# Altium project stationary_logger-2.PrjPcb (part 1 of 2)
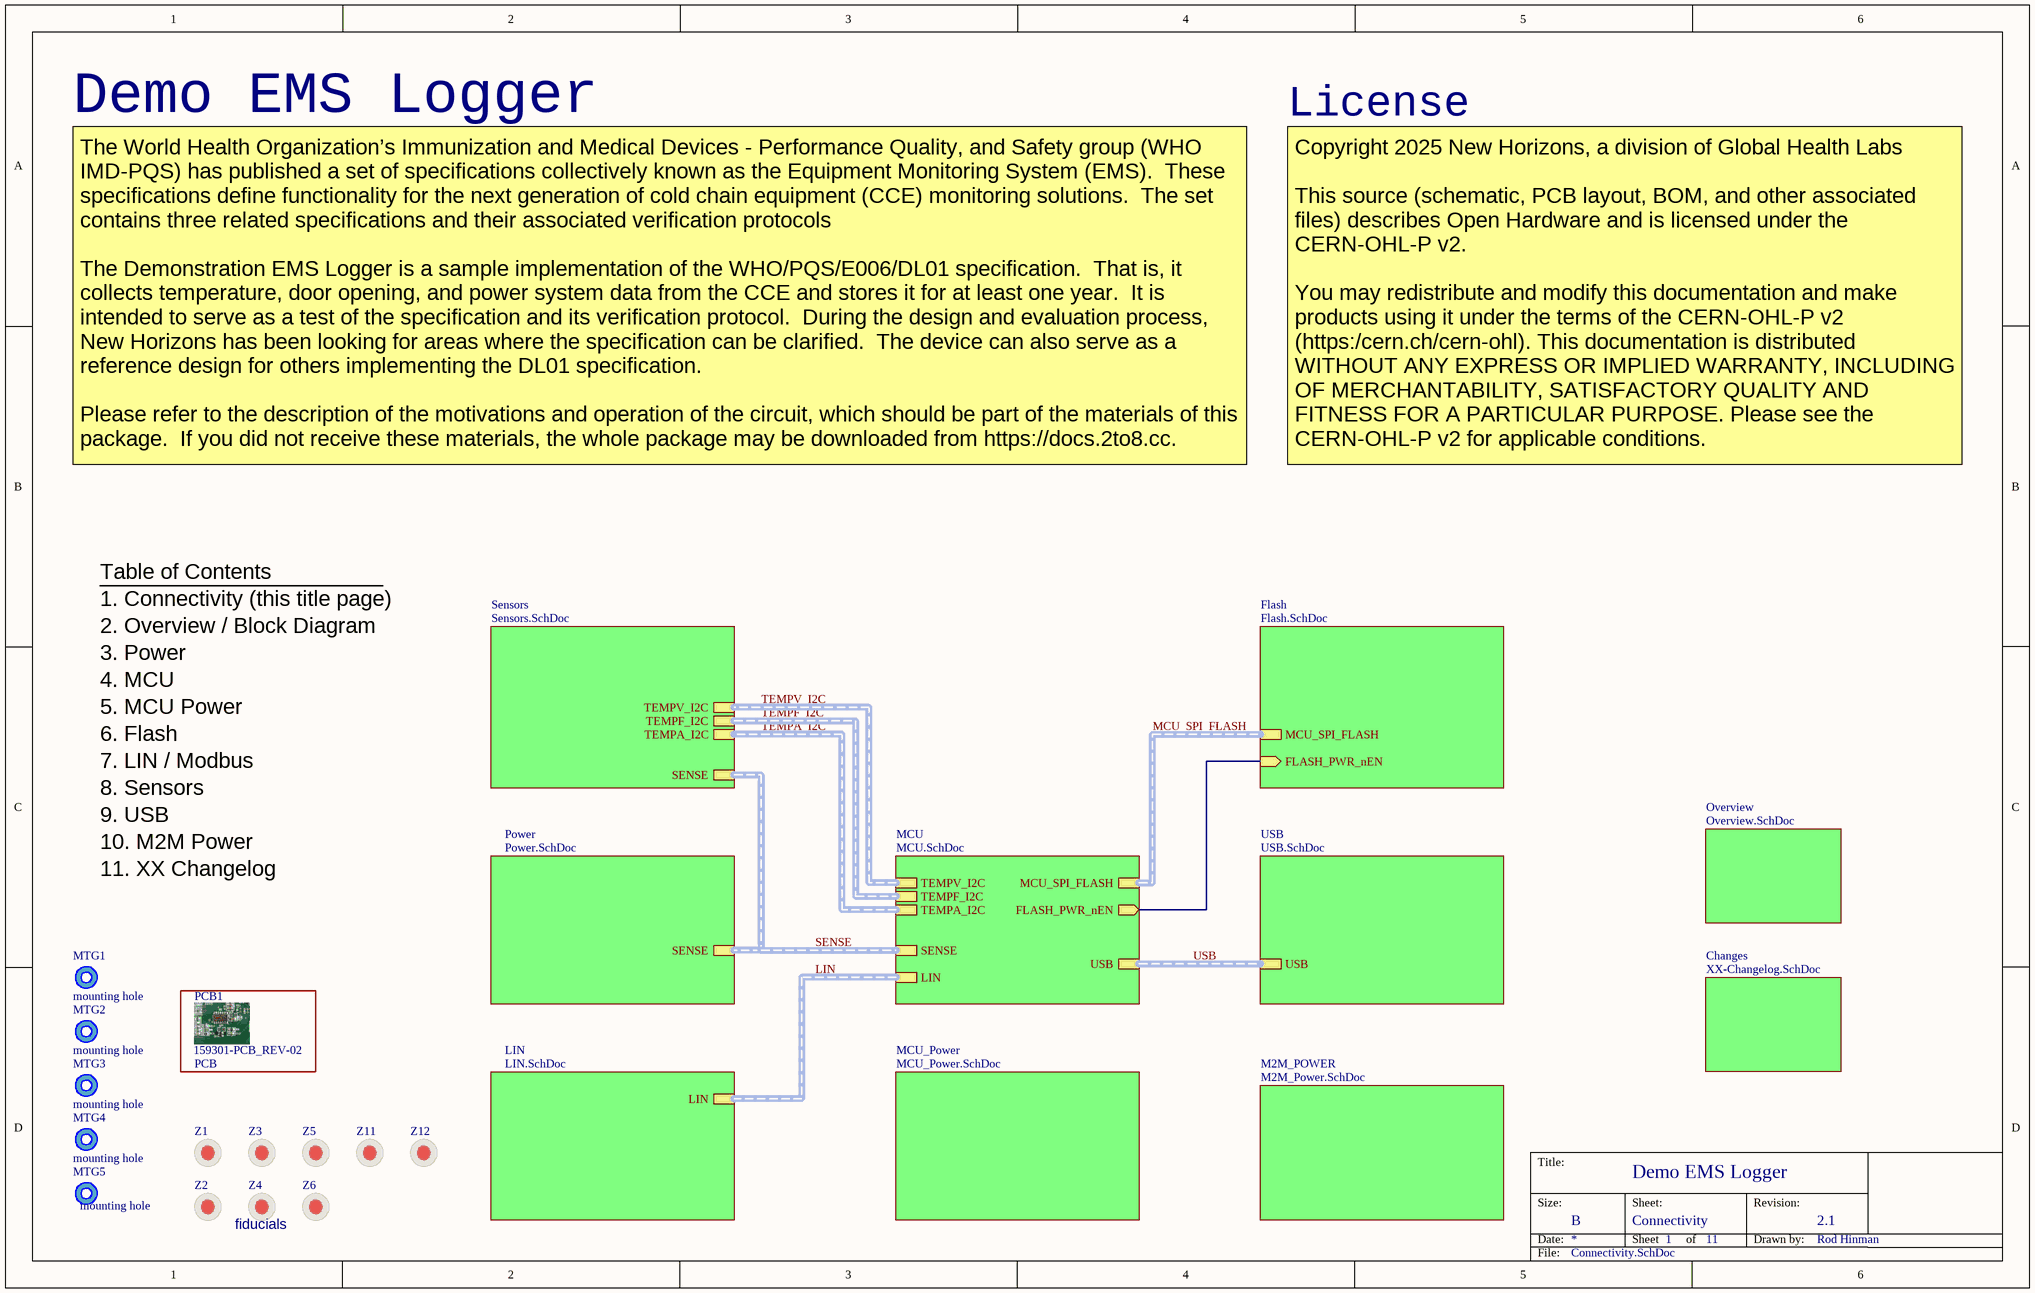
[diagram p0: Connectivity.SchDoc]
nhToday: 2025-05-20; nhProjRev: 2.1; nhProjName: Demo EMS Logger; nhEngPhone: +1 808-989-0977; nhEngName: Rod Hinman; nhEngEmail: rhinman@nhgh.org
11 sheets, 319 parts. Net scope: hierarchical (ports join the sheet entries above them; power ports are global).
Board file: stationary_logger-2.PcbDoc
Sheets:
  Connectivity.SchDoc
    MCU = MCU.SchDoc
    Power = Power.SchDoc
    LIN = LIN.SchDoc
    Sensors = Sensors.SchDoc
    Flash = Flash.SchDoc
    MCU_Power = MCU_Power.SchDoc
    USB = USB.SchDoc
    Changes = XX-Changelog.SchDoc
    Overview = Overview.SchDoc
    M2M_POWER = M2M_Power.SchDoc

## Sheet Connectivity.SchDoc: Insert Title
size B; DrawnBy: Insert Name; Organization: NH-GG; DocumentNumber: 12345; Revision: 1; SheetNumber: 1; SheetTotal: 11; nhSheetName: Connectivity

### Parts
MTG1  mounting hole  [MOUNT_HOLE_3MM_NOCOPPER]  (no BOM)
MTG2  mounting hole  [MOUNT_HOLE_3MM_NOCOPPER]  (no BOM)
MTG3  mounting hole  [MOUNT_HOLE_3MM_NOCOPPER]  (no BOM)
MTG4  mounting hole  [MOUNT_HOLE_3MM_NOCOPPER]  (no BOM)
MTG5  mounting hole  [MOUNT_HOLE_3MM_NOCOPPER]  (no BOM)
PCB1  PCB  manufacturer_pn: 159301-PCB_REV-02  (mechanical)
Z1  NOBOM-00010  [FIDUCIAL_1_3_KEEPOUT]  (value not drawn)  (no BOM)
Z2  NOBOM-00010  [FIDUCIAL_1_3_KEEPOUT]  (value not drawn)  (no BOM)
Z3  NOBOM-00010  [FIDUCIAL_1_3_KEEPOUT]  (value not drawn)  (no BOM)
Z4  NOBOM-00010  [FIDUCIAL_1_3_KEEPOUT]  (value not drawn)  (no BOM)
Z5  NOBOM-00010  [FIDUCIAL_1_3_KEEPOUT]  (value not drawn)  (no BOM)
Z6  NOBOM-00010  [FIDUCIAL_1_3_KEEPOUT]  (value not drawn)  (no BOM)
Z11  NOBOM-00010  [FIDUCIAL_1_3_KEEPOUT]  (value not drawn)  (no BOM)
Z12  NOBOM-00010  [FIDUCIAL_1_3_KEEPOUT]  (value not drawn)  (no BOM)

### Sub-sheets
Changes = XX-Changelog.SchDoc: no entries
Flash = Flash.SchDoc: FLASH_PWR_nEN (in), MCU_SPI_FLASH (harness SPI)
LIN = LIN.SchDoc: LIN (harness lin)
M2M_POWER = M2M_Power.SchDoc: no entries
MCU = MCU.SchDoc: LIN (harness lin), SENSE (harness sense), USB (harness usb), MCU_SPI_FLASH (harness SPI), FLASH_PWR_nEN (out), TEMPF_I2C (harness I2C), TEMPA_I2C (harness I2C), TEMPV_I2C (harness I2C)
MCU_Power = MCU_Power.SchDoc: no entries
Overview = Overview.SchDoc: no entries
Power = Power.SchDoc: SENSE (harness sense)
Sensors = Sensors.SchDoc: TEMPF_I2C (harness I2C), SENSE (harness sense), TEMPA_I2C (harness I2C), TEMPV_I2C (harness I2C)
USB = USB.SchDoc: USB (harness usb)

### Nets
FLASH_PWR_nEN: sheet MCU/FLASH_PWR_nEN, sheet Flash/FLASH_PWR_nEN

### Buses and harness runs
harness LIN = sheet LIN/LIN = sheet MCU/LIN
harness MCU_SPI_FLASH = sheet Flash/MCU_SPI_FLASH = sheet MCU/MCU_SPI_FLASH
harness SENSE = sheet MCU/SENSE = sheet Power/SENSE = sheet Sensors/SENSE
harness TEMPA_I2C = sheet MCU/TEMPA_I2C = sheet Sensors/TEMPA_I2C
harness TEMPF_I2C = sheet MCU/TEMPF_I2C = sheet Sensors/TEMPF_I2C
harness TEMPV_I2C = sheet MCU/TEMPV_I2C = sheet Sensors/TEMPV_I2C
harness USB = sheet MCU/USB = sheet USB/USB

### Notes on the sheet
- Demo EMS Logger
- License
- The World Health Organization’s Immunization and Medical Devices - Performance Quality, and Safety group (WHO IMD-PQS) has published a set of specifications collectively known as the Equipment Monitoring System (EMS).  These specifications define functionality for the next generation of cold chain equipment (CCE) monitoring solutions.  The set contains three related specifications and their associated verification protocols
  The Demonstration EMS Logger is a sample implementation of the WHO/PQS/E006/DL01 specification.  That is, it collects temperature, door opening, and power system data from the CCE and stores it for at least one year.  It is intended to serve as a test of the specification and its verification protocol.  During the design and evaluation process, New Horizons has been looking for areas where the specification can be clarified.  The device can also serve as a reference design for others implementing the DL01 specification.
  Please refer to the description of the motivations and operation of the circuit, which should be part of the materials of this package.  If you did not receive these materials, the whole package may be downloaded from https://docs.2to8.cc.
- Copyright 2025 New Horizons, a division of Global Health Labs
  This source (schematic, PCB layout, BOM, and other associated files) describes Open Hardware and is licensed under the CERN-OHL-P v2.
  You may redistribute and modify this documentation and make products using it under the terms of the CERN-OHL-P v2 (https:/cern.ch/cern-ohl). This documentation is distributed WITHOUT ANY EXPRESS OR IMPLIED WARRANTY, INCLUDING OF MERCHANTABILITY, SATISFACTORY QUALITY AND FITNESS FOR A PARTICULAR PURPOSE. Please see the CERN-OHL-P v2 for applicable conditions.
- Table of Contents
- 1. Connectivity (this title page)
- 2. Overview / Block Diagram
- 3. Power
- 4. MCU
- 6. Flash
- 7. LIN / Modbus
- 5. MCU Power
- 8. Sensors
- 9. USB
- 10. M2M Power
- 11. XX Changelog
- fiducials

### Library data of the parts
MTG1-MTG5 = NOBOM-00023: Mounting hole, 3mm NPT; manufacturer: New Horizons; id: 477843
PCB1 = MECH-00042: PCB - enter your own cost; manufacturer: New Horizons; id: 408762
Z1-Z6 Z11 Z12 = NOBOM-00010: Fiducial, 1mm dia, 3mm solder mask opening; manufacturer: New Horizons; id: 138118

## Sheet MCU.SchDoc: Insert Title
size B; DrawnBy: Insert Name; Organization: NH-GG; DocumentNumber: 12345; Revision: 1; SheetNumber: 4; SheetTotal: 11; nhSheetName: MCU
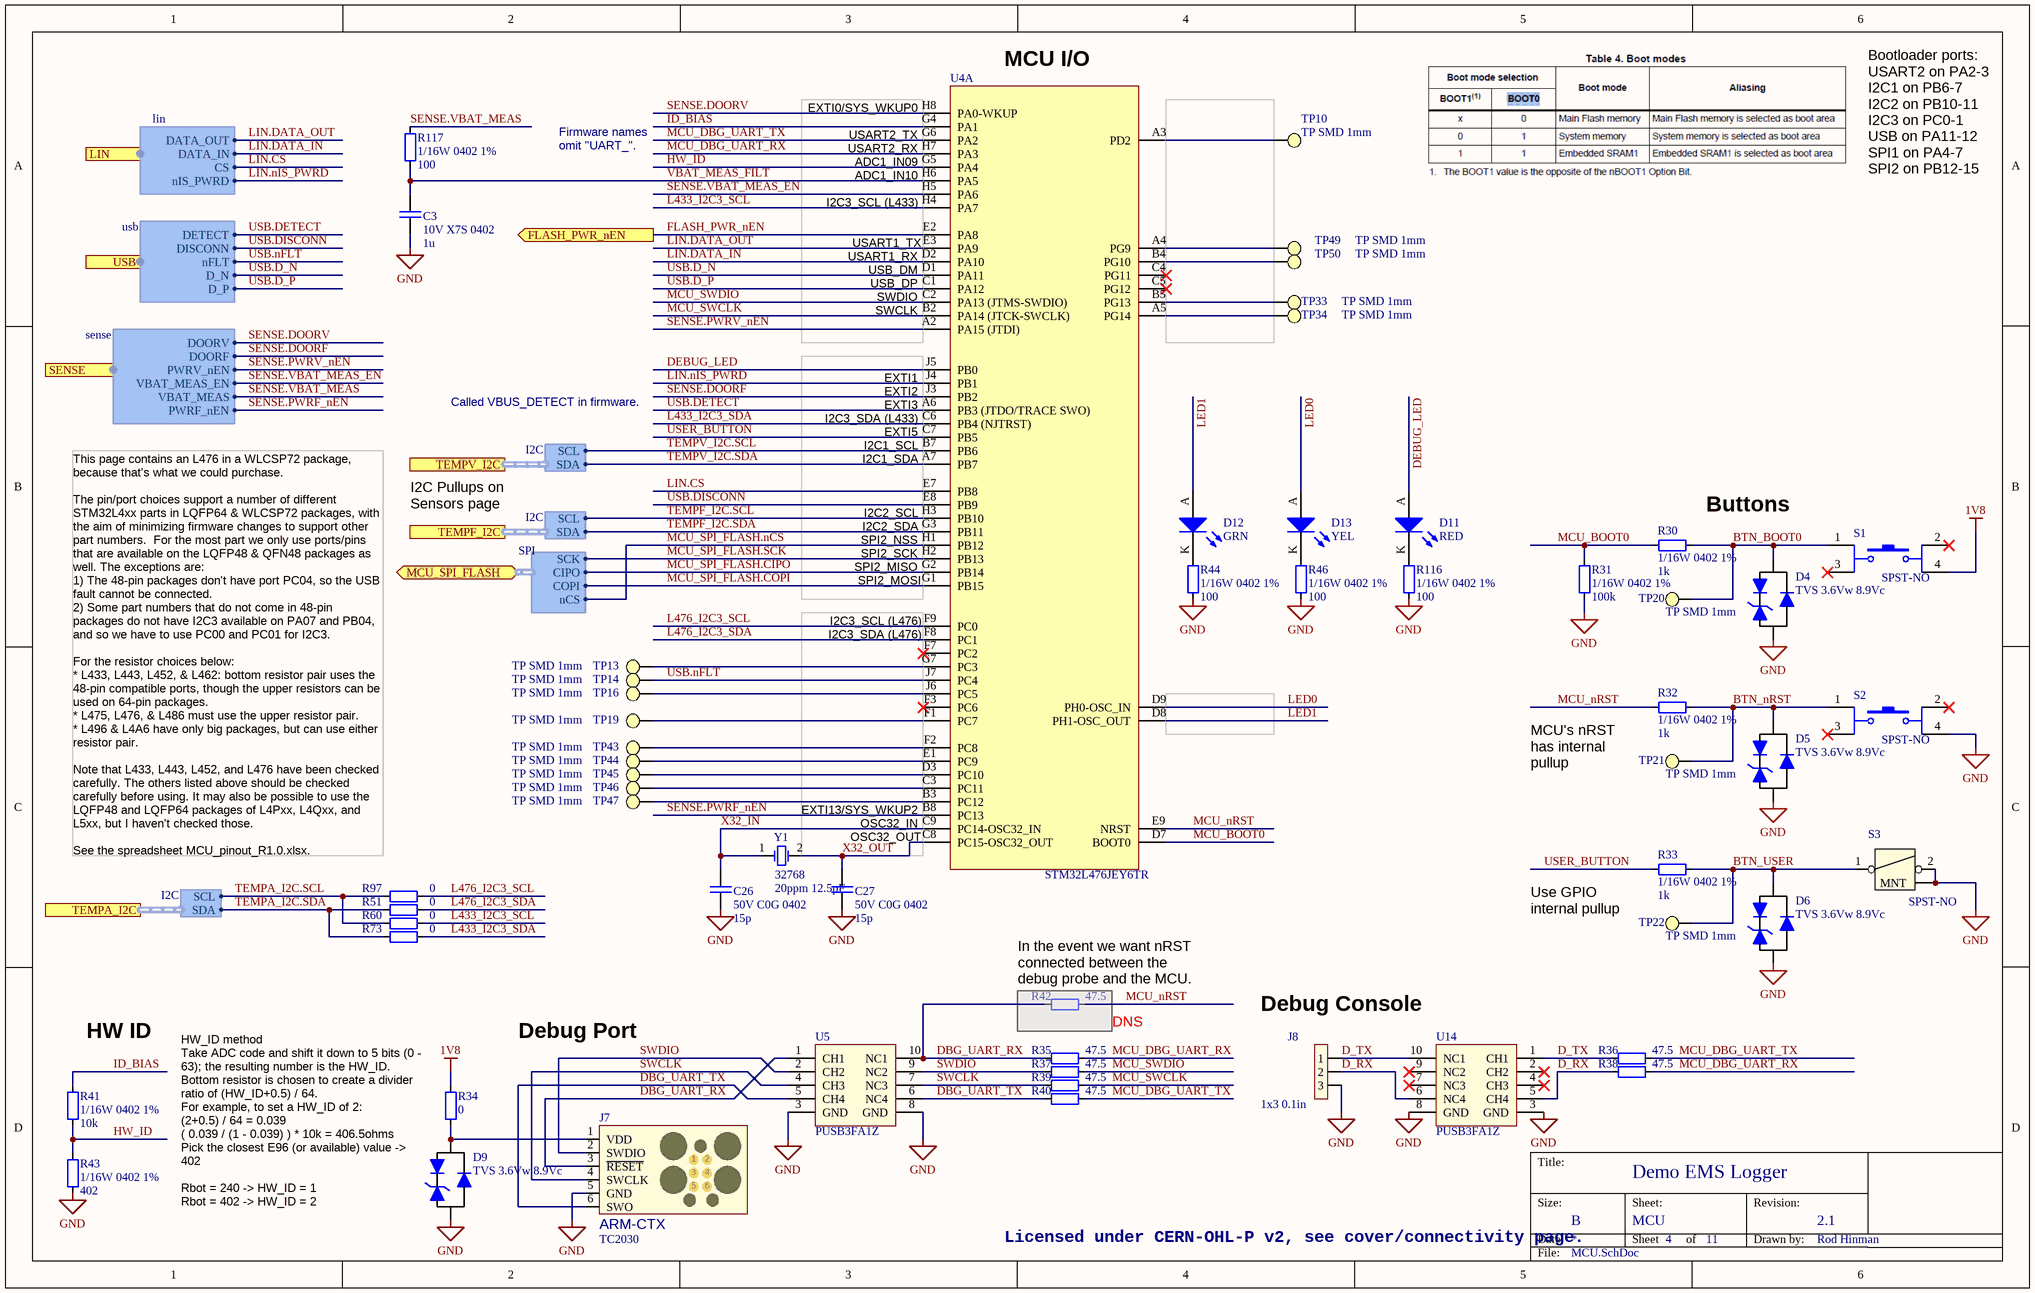
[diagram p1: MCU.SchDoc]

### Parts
C3  10V X7S 0402  value_text: 1u  [CAPC1005X55,0402,L]
C26  50V C0G 0402  value_text: 15p  [CAPC1005X60,0402,L]
C27  50V C0G 0402  value_text: 15p  [CAPC1005X60,0402,L]
D4  TVS 3.6Vw 8.9Vc  [TI_2-X1SON_DFN65P100X60-2L]
D5  TVS 3.6Vw 8.9Vc  [TI_2-X1SON_DFN65P100X60-2L]
D6  TVS 3.6Vw 8.9Vc  [TI_2-X1SON_DFN65P100X60-2L]
D9  TVS 3.6Vw 8.9Vc  [TI_2-X1SON_DFN65P100X60-2L]
D11  RED  [LEDC1005X04NRED,0402,]
D12  GRN  [LEDC1608X06NGRN,0603,]
D13  YEL  [LEDC1608X06NYEL,0603,]
J7  TC2030  [TAG-TC2030-LEGS]  (no BOM)
J8  1x3 0.1in  [HDR_3PIN]
R30  1/16W 0402 1%  value_text: 1k  [RESC1005X40,0402,L]
R31  1/16W 0402 1%  value_text: 100k  [RESC1005X40,0402,L]
R32  1/16W 0402 1%  value_text: 1k  [RESC1005X40,0402,L]
R33  1/16W 0402 1%  value_text: 1k  [RESC1005X40,0402,L]
R34  value_text: 0  [RESC1005X40,0402,L]  (hidden comment: 1/16W 0402 Jumper)
R35  value_text: 47.5  [RESC1005X40,0402,L]  (hidden comment: 1/16W 0402 1%)
R36  value_text: 47.5  [RESC1005X40,0402,L]  (hidden comment: 1/16W 0402 1%)
R37  value_text: 47.5  [RESC1005X40,0402,L]  (hidden comment: 1/16W 0402 1%)
R38  value_text: 47.5  [RESC1005X40,0402,L]  (hidden comment: 1/16W 0402 1%)
R39  value_text: 47.5  [RESC1005X40,0402,L]  (hidden comment: 1/16W 0402 1%)
R40  value_text: 47.5  [RESC1005X40,0402,L]  (hidden comment: 1/16W 0402 1%)
R41  1/16W 0402 1%  value_text: 10k  [RESC1005X40,0402,L]
R42  value_text: 47.5  [RESC1005X40,0402,L]  (hidden comment: 1/16W 0402 1%)
R43  1/16W 0402 1%  value_text: 402  [RESC1005X40,0402,L]
R44  1/16W 0402 1%  value_text: 100  [RESC1005X40,0402,L]
R46  1/16W 0402 1%  value_text: 100  [RESC1005X40,0402,L]
R51  value_text: 0  [RESC1005X40,0402,L]  (hidden comment: 1/16W 0402 Jumper)
R60  value_text: 0  [RESC1005X40,0402,L]  (hidden comment: 1/16W 0402 Jumper)
R73  value_text: 0  [RESC1005X40,0402,L]  (hidden comment: 1/16W 0402 Jumper)
R97  value_text: 0  [RESC1005X40,0402,L]  (hidden comment: 1/16W 0402 Jumper)
R116  1/16W 0402 1%  value_text: 100  [RESC1005X40,0402,L]
R117  1/16W 0402 1%  value_text: 100  [RESC1005X40,0402,L]
S1  SPST-NO  [EVQP2x02W_MIRROR]
S2  SPST-NO  [EVQP2x02W_MIRROR]
S3  SPST-NO  [TE_1571300]
TP10  TP SMD 1mm  [TP_SMD_Ø1.0mm NO SILK]  (no BOM)
TP13  TP SMD 1mm  [TP_SMD_Ø1.0mm NO SILK]  (no BOM)
TP14  TP SMD 1mm  [TP_SMD_Ø1.0mm NO SILK]  (no BOM)
TP16  TP SMD 1mm  [TP_SMD_Ø1.0mm NO SILK]  (no BOM)
TP19  TP SMD 1mm  [TP_SMD_Ø1.0mm NO SILK]  (no BOM)
TP20  TP SMD 1mm  [TP_SMD_Ø1.0mm NO SILK]  (no BOM)
TP21  TP SMD 1mm  [TP_SMD_Ø1.0mm NO SILK]  (no BOM)
TP22  TP SMD 1mm  [TP_SMD_Ø1.0mm NO SILK]  (no BOM)
TP33  TP SMD 1mm  [TP_SMD_Ø1.0mm NO SILK]  (no BOM)
TP34  TP SMD 1mm  [TP_SMD_Ø1.0mm NO SILK]  (no BOM)
TP43  TP SMD 1mm  [TP_SMD_Ø1.0mm NO SILK]  (no BOM)
TP44  TP SMD 1mm  [TP_SMD_Ø1.0mm NO SILK]  (no BOM)
TP45  TP SMD 1mm  [TP_SMD_Ø1.0mm NO SILK]  (no BOM)
TP46  TP SMD 1mm  [TP_SMD_Ø1.0mm NO SILK]  (no BOM)
TP47  TP SMD 1mm  [TP_SMD_Ø1.0mm NO SILK]  (no BOM)
TP49  TP SMD 1mm  [TP_SMD_Ø1.0mm NO SILK]  (no BOM)
TP50  TP SMD 1mm  [TP_SMD_Ø1.0mm NO SILK]  (no BOM)
U4  STM32L476JEY6TR  [STM_BGA72C40P9X9_441X376X58]  (part A of 2)
U5  PUSB3FA1Z  [NEXPERIA_DFN2510_50p250x100x50-10]
U14  PUSB3FA1Z  [NEXPERIA_DFN2510_50p250x100x50-10]
Y1  20ppm 12.5pF  value_text: 32768  [FC-135]

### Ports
FLASH_PWR_nEN (out), LIN (out, harness lin), MCU_SPI_FLASH (bidir, harness SPI), SENSE (out, harness sense), TEMPA_I2C (harness I2C), TEMPF_I2C (harness I2C), TEMPV_I2C (harness I2C), USB (out, harness usb)

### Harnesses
SPI: CIPO, COPI, SCK, nCS
I2C: SCL, SDA
lin: DATA_OUT, DATA_IN, CS, nIS_PWRD
usb: DETECT, DISCONN, D_N, D_P, nFLT
sense: DOORV, DOORF, PWRV_nEN, VBAT_MEAS_EN, VBAT_MEAS, PWRF_nEN

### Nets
1V8: R34.1 S1.4
GND: C3.1 C26.1 C27.1 D4.2 D5.2 D6.2 D9.2 J7.5(GND) J8.3 R31.2 R43.2 R44.1 R46.1 R116.1 S2.4 S3.2 S3.MNT U5.3(GND) U5.8(GND) U14.3(GND) U14.8(GND)
BTN_BOOT0: D4.1 R30.2 S1.1 TP20.1
BTN_nRST: D5.1 R32.2 S2.1 TP21.1
BTN_USER: D6.1 R33.2 S3.1 TP22.1
D_RX: J8.2 R38.1 U14.5(CH4) U14.6(NC4)
D_TX: J8.1 R36.1 U14.1(CH1) U14.10(NC1)
DBG_UART_RX: J7.3(~{RESET}) R35.1 R42.2 U5.1(CH1) U5.10(NC1)
DBG_UART_TX: J7.6(SWO) R40.1 U5.5(CH4) U5.6(NC4)
DEBUG_LED: D11.A U4.J5(PB0)
FLASH_PWR_nEN: U4.E2(PA8) ; port FLASH_PWR_nEN
HW_ID: R41.2 R43.1 U4.G5(PA4)
ID_BIAS: R41.1 U4.G4(PA1)
L433_I2C3_SCL: R60.1 U4.H4(PA7)
L433_I2C3_SDA: R73.1 U4.C6(PB4_(NJTRST))
L476_I2C3_SCL: R97.1 U4.F9(PC0)
L476_I2C3_SDA: R51.1 U4.F8(PC1)
LED0: D13.A U4.D9(PH0-OSC_IN)
LED1: D12.A U4.D8(PH1-OSC_OUT)
LIN.CS: U4.E7(PB8) ; port LIN.CS
LIN.DATA_IN: U4.D2(PA10) ; port LIN.DATA_IN
LIN.DATA_OUT: U4.E3(PA9) ; port LIN.DATA_OUT
LIN.nIS_PWRD: U4.J4(PB1) ; port LIN.nIS_PWRD
MCU_BOOT0: R30.1 R31.1 U4.D7(BOOT0)
MCU_DBG_UART_RX: R35.2 R38.2 U4.H7(PA3)
MCU_DBG_UART_TX: R36.2 R40.2 U4.G6(PA2)
MCU_nRST: R32.1 R42.1 U4.E9(NRST)
MCU_SPI_FLASH.CIPO: U4.G2(PB14) ; port MCU_SPI_FLASH.CIPO
MCU_SPI_FLASH.COPI: U4.G1(PB15) ; port MCU_SPI_FLASH.COPI
MCU_SPI_FLASH.nCS: U4.H1(PB12) ; port MCU_SPI_FLASH.nCS
MCU_SPI_FLASH.SCK: U4.H2(PB13) ; port MCU_SPI_FLASH.SCK
MCU_SWCLK: R39.2 U4.B2(PA14_(JTCK-SWCLK))
MCU_SWDIO: R37.2 U4.C2(PA13_(JTMS-SWDIO))
SENSE.DOORF: U4.J3(PB2) ; port SENSE.DOORF
SENSE.DOORV: U4.H8(PA0-WKUP) ; port SENSE.DOORV
SENSE.PWRF_nEN: U4.B8(PC13) ; port SENSE.PWRF_nEN
SENSE.PWRV_nEN: U4.A2(PA15_(JTDI)) ; port SENSE.PWRV_nEN
SENSE.VBAT_MEAS: R117.2 ; port SENSE.VBAT_MEAS
SENSE.VBAT_MEAS_EN: U4.H5(PA6) ; port SENSE.VBAT_MEAS_EN
SWCLK: J7.4(SWCLK) R39.1 U5.4(CH3) U5.7(NC3)
SWDIO: J7.2(SWDIO) R37.1 U5.2(CH2) U5.9(NC2)
TEMPA_I2C.SCL: R60.2 R97.2 ; port TEMPA_I2C.SCL
TEMPA_I2C.SDA: R51.2 R73.2 ; port TEMPA_I2C.SDA
TEMPF_I2C.SCL: U4.H3(PB10) ; port TEMPF_I2C.SCL
TEMPF_I2C.SDA: U4.G3(PB11) ; port TEMPF_I2C.SDA
TEMPV_I2C.SCL: U4.B7(PB6) ; port TEMPV_I2C.SCL
TEMPV_I2C.SDA: U4.A7(PB7) ; port TEMPV_I2C.SDA
USB.D_N: U4.D1(PA11) ; port USB.D_N
USB.D_P: U4.C1(PA12) ; port USB.D_P
USB.DETECT: U4.A6(PB3_(JTDO/TRACE_SWO)) ; port USB.DETECT
USB.DISCONN: U4.E8(PB9) ; port USB.DISCONN
USB.nFLT: TP14.1 U4.J7(PC4) ; port USB.nFLT
USER_BUTTON: R33.1 U4.C7(PB5)
VBAT_MEAS_FILT: C3.2 R117.1 U4.H6(PA5)
X32_IN: C26.2 U4.C9(PC14-OSC32_IN) Y1.1(OSC1)
X32_OUT: C27.2 U4.C8(PC15-OSC32_OUT) Y1.2(OSC2)
NetD9_1: D9.1 J7.1(VDD) R34.2
NetD11_K: D11.K R116.2
NetD12_K: D12.K R44.2
NetD13_K: D13.K R46.2
NetTP10_1: TP10.1 U4.A3(PD2)
NetTP13_1: TP13.1 U4.G7(PC3)
NetTP16_1: TP16.1 U4.J6(PC5)
NetTP19_1: TP19.1 U4.F1(PC7)
NetTP33_1: TP33.1 U4.B5(PG13)
NetTP34_1: TP34.1 U4.A5(PG14)
NetTP43_1: TP43.1 U4.F2(PC8)
NetTP44_1: TP44.1 U4.E1(PC9)
NetTP45_1: TP45.1 U4.D3(PC10)
NetTP46_1: TP46.1 U4.C3(PC11)
NetTP47_1: TP47.1 U4.B3(PC12)
NetTP49_1: TP49.1 U4.A4(PG9)
NetTP50_1: TP50.1 U4.B4(PG10)

Not connected (* = marked no-connect by the designer): S1 2* 3*; S2 2* 3*; U4 C4(PG11)* C5(PG12)* F3(PC6)* F7(PC2)*; U14 2(CH2)* 4(CH3)* 7(NC3)* 9(NC2)*

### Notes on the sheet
- (near U4) MCU I/O
- Firmware names
- omit "UART_".
- Bootloader ports:
  USART2 on PA2-3
  I2C1 on PB6-7
  I2C2 on PB10-11
  I2C3 on PC0-1
  USB on PA11-12
  SPI1 on PA4-7
  SPI2 on PB12-15
- (near U4) EXTI0/SYS_WKUP0
  USART2_TX
  USART2_RX
  ADC1_IN09
  ADC1_IN10
  I2C3_SCL (L433)
  USART1_TX
  USART1_RX
  USB_DM
  USB_DP
  SWDIO
  SWCLK
- Called VBUS_DETECT in firmware.
- I2C Pullups on Sensors page
- Buttons
- (near U4) EXTI1
  EXTI2
  EXTI3
  I2C3_SDA (L433)
  EXTI5
  I2C1_SCL
  I2C1_SDA
  I2C2_SCL
  I2C2_SDA
  SPI2_NSS
  SPI2_SCK
  SPI2_MISO
  SPI2_MOSI
- MCU's nRST has internal pullup
- This page contains an L476 in a WLCSP72 package, because that's what we could purchase.
  The pin/port choices support a number of different STM32L4xx parts in LQFP64 & WLCSP72 packages, with the aim of minimizing firmware changes to support other part numbers.  For the most part we only use ports/pins that are available on the LQFP48 & QFN48 packages as well. The exceptions are:
  1) The 48-pin packages don't have port PC04, so the USB fault cannot be connected.
  2) Some part numbers that do not come in 48-pin packages do not have I2C3 available on PA07 and PB04, and so we have to use PC00 and PC01 for I2C3.
  For the resistor choices below:
  * L433, L443, L452, & L462: bottom resistor pair uses the 48-pin compatible ports, though the upper resistors can be used on 64-pin packages.
  * L475, L476, & L486 must use the upper resistor pair.
  * L496 & L4A6 have only big packages, but can use either resistor pair.
  Note that L433, L443, L452, and L476 have been checked carefully. The others listed above should be checked carefully before using. It may also be possible to use the LQFP48 and LQFP64 packages of L4Pxx, L4Qxx, and L5xx, but I haven't checked those.
  See the spreadsheet MCU_pinout_R1.0.xlsx.
- (near Y1) I2C3_SCL (L476)
  I2C3_SDA (L476)
  EXTI13/SYS_WKUP2
  OSC32_IN
  OSC32_OUT
- Use GPIO internal pullup
- (near R41) HW ID
- Debug Port
- (near R42) In the event we want nRST connected between the debug probe and the MCU.
- (near R42) DNS
- Debug Console
- HW_ID method
  Take ADC code and shift it down to 5 bits (0 - 63); the resulting number is the HW_ID. Bottom resistor is chosen to create a divider ratio of (HW_ID+0.5) / 64.
  For example, to set a HW_ID of 2:
  (2+0.5) / 64 = 0.039
  ( 0.039 / (1 - 0.039) ) * 10k = 406.5ohms
  Pick the closest E96 (or available) value -> 402
  Rbot = 240 -> HW_ID = 1
  Rbot = 402 -> HW_ID = 2
- Licensed under CERN-OHL-P v2, see cover/connectivity page.

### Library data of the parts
C3 = CAP-00070: 1µF ±10% 10V Ceramic Capacitor X7S 0402 (1005 Metric); manufacturer_pn: GCM155C71A105KE38D; manufacturer: Murata Electronics North America; id: 168187; value: 1E-6
C26 C27 = CAP-00102: 15pF ±1% 50V Ceramic Capacitor C0G, NP0 0402 (1005 Metric); manufacturer_pn: 04025U150FAT2A; manufacturer: AVX Corporation; id: 226036; value: 1.5E-11
D4-D6 D9 = DIO-00055: TVS DIODE 3.6VWM 8.9VC 2X1SON; manufacturer_pn: TPD1E04U04DPYR; manufacturer: Texas Instruments; id: 468103
D11 = LED-00025: LED RED CLEAR 0402 SMD; manufacturer_pn: SML-P12VTT86R; manufacturer: Rohm Semiconductor; id: 468105
D12 = LED-00007: Green 571nm LED Indication - Discrete 2V 0603 (1608 Metric) 35mcd clear; manufacturer_pn: LTST-C191KGKT; manufacturer: Lite-On Inc.; id: 137520
D13 = LED-00006: Yellow 591nm LED Indication - Discrete 2.1V 0603 (1608 Metric) 104mcd clear; manufacturer_pn: LTST-C191KSKT; manufacturer: Lite-On Inc.; id: 137519
J7 = NOBOM-00009: Tag Connect TC2030 LEGS; manufacturer: New Horizons; id: 138117
J8 = CONN-00030: 3 Positions Header, Unshrouded Connector 0.100" (2.54mm) Through Hole Gold; manufacturer_pn: 961103-6404-AR; manufacturer: 3M; id: 137495
R30 R32 R33 = RES-00090: 1k Ohm ±1% 0.063W, 1/16W Chip Resistor 0402 (1005 Metric) Moisture Resistant Thick Film; manufacturer_pn: RC0402FR-071KL; manufacturer: Yageo; id: 168133; value: 1000
R31 = RES-00095: 100k Ohm ±1% 0.063W, 1/16W Chip Resistor 0402 (1005 Metric) Moisture Resistant Thick Film; manufacturer_pn: RC0402FR-07100KL; manufacturer: Yageo; id: 168197; value: 100000
R34 R51 R60 R73 R97 = RES-00093: 0.0 Ohm Jumper 0.063W, 1/16W Chip Resistor 0402 (1005 Metric) Moisture Resistant Thick Film; manufacturer_pn: RC0402JR-070RL; manufacturer: Yageo; id: 168185; value: 0
R35-R40 R42 = RES-00169: 47.5 ±1% 0.063W, 1/16W Chip Resistor 0402 (1005 Metric) - Thick Film; manufacturer_pn: RC0402FR-0747R5L; manufacturer: Yageo; id: 406782; value: 47.5
R41 = RES-00094: 10k Ohm ±1% 0.063W, 1/16W Chip Resistor 0402 (1005 Metric) Moisture Resistant Thick Film; manufacturer_pn: RC0402FR-0710KL; manufacturer: Yageo; id: 168195; value: 10000
R43 = RES-00203: RES 402 OHM 1% 1/16W 0402; manufacturer_pn: RC0402FR-07402RL; manufacturer: Yageo; id: 472313; value: 402; reorder_quantity: 0
R44 R46 R116 R117 = RES-00111: 100 Ohms ±1% 0.063W, 1/16W Chip Resistor 0402 (1005 Metric) Moisture Resistant Thick Film; manufacturer_pn: RC0402FR-07100RL; manufacturer: Yageo; id: 184628; value: 100
S1 S2 = SW-00011: Tactile Switch SPST-NO Top Actuated Surface Mount; manufacturer_pn: EVQ-P2402W; manufacturer: Panasonic Electronic Components; id: 468174
S3 = SW-00012: SWITCH TACTILE SPST-NO 0.05A 24V; manufacturer_pn: 1571300-2; manufacturer: TE Connectivity ALCOSWITCH Switches; id: 477187
TP10 TP13 TP14 TP16 TP19-TP22 TP33 TP34 TP43-TP47 TP49 TP50 = NOBOM-00001: Test point, SMD, 1mm dia (0.040"); manufacturer: New Horizons; id: 137197
U4 = MCU-00028: IC MCU 32BIT 512KB FLASH WLCSP72; manufacturer: STMicroelectronics; id: 474854
U5 U14 = DIO-00056: TVS DIODE 3VC DFN2510A-10; manufacturer: Nexperia USA Inc.; id: 468220
Y1 = XTAL-00000: 32.768kHz ±20ppm Crystal 12.5pF 55 kOhm -40°C ~ 85°C Surface Mount 2-SMD; manufacturer_pn: ABS07L-32.768KHZ-T; manufacturer: Abracon LLC; id: 136552; value: 32768

## Sheet Power.SchDoc: Insert Title
size B; DrawnBy: Insert Name; Organization: NH-GG; DocumentNumber: 12345; Revision: 1; SheetNumber: 3; SheetTotal: 11; nhSheetName: Power
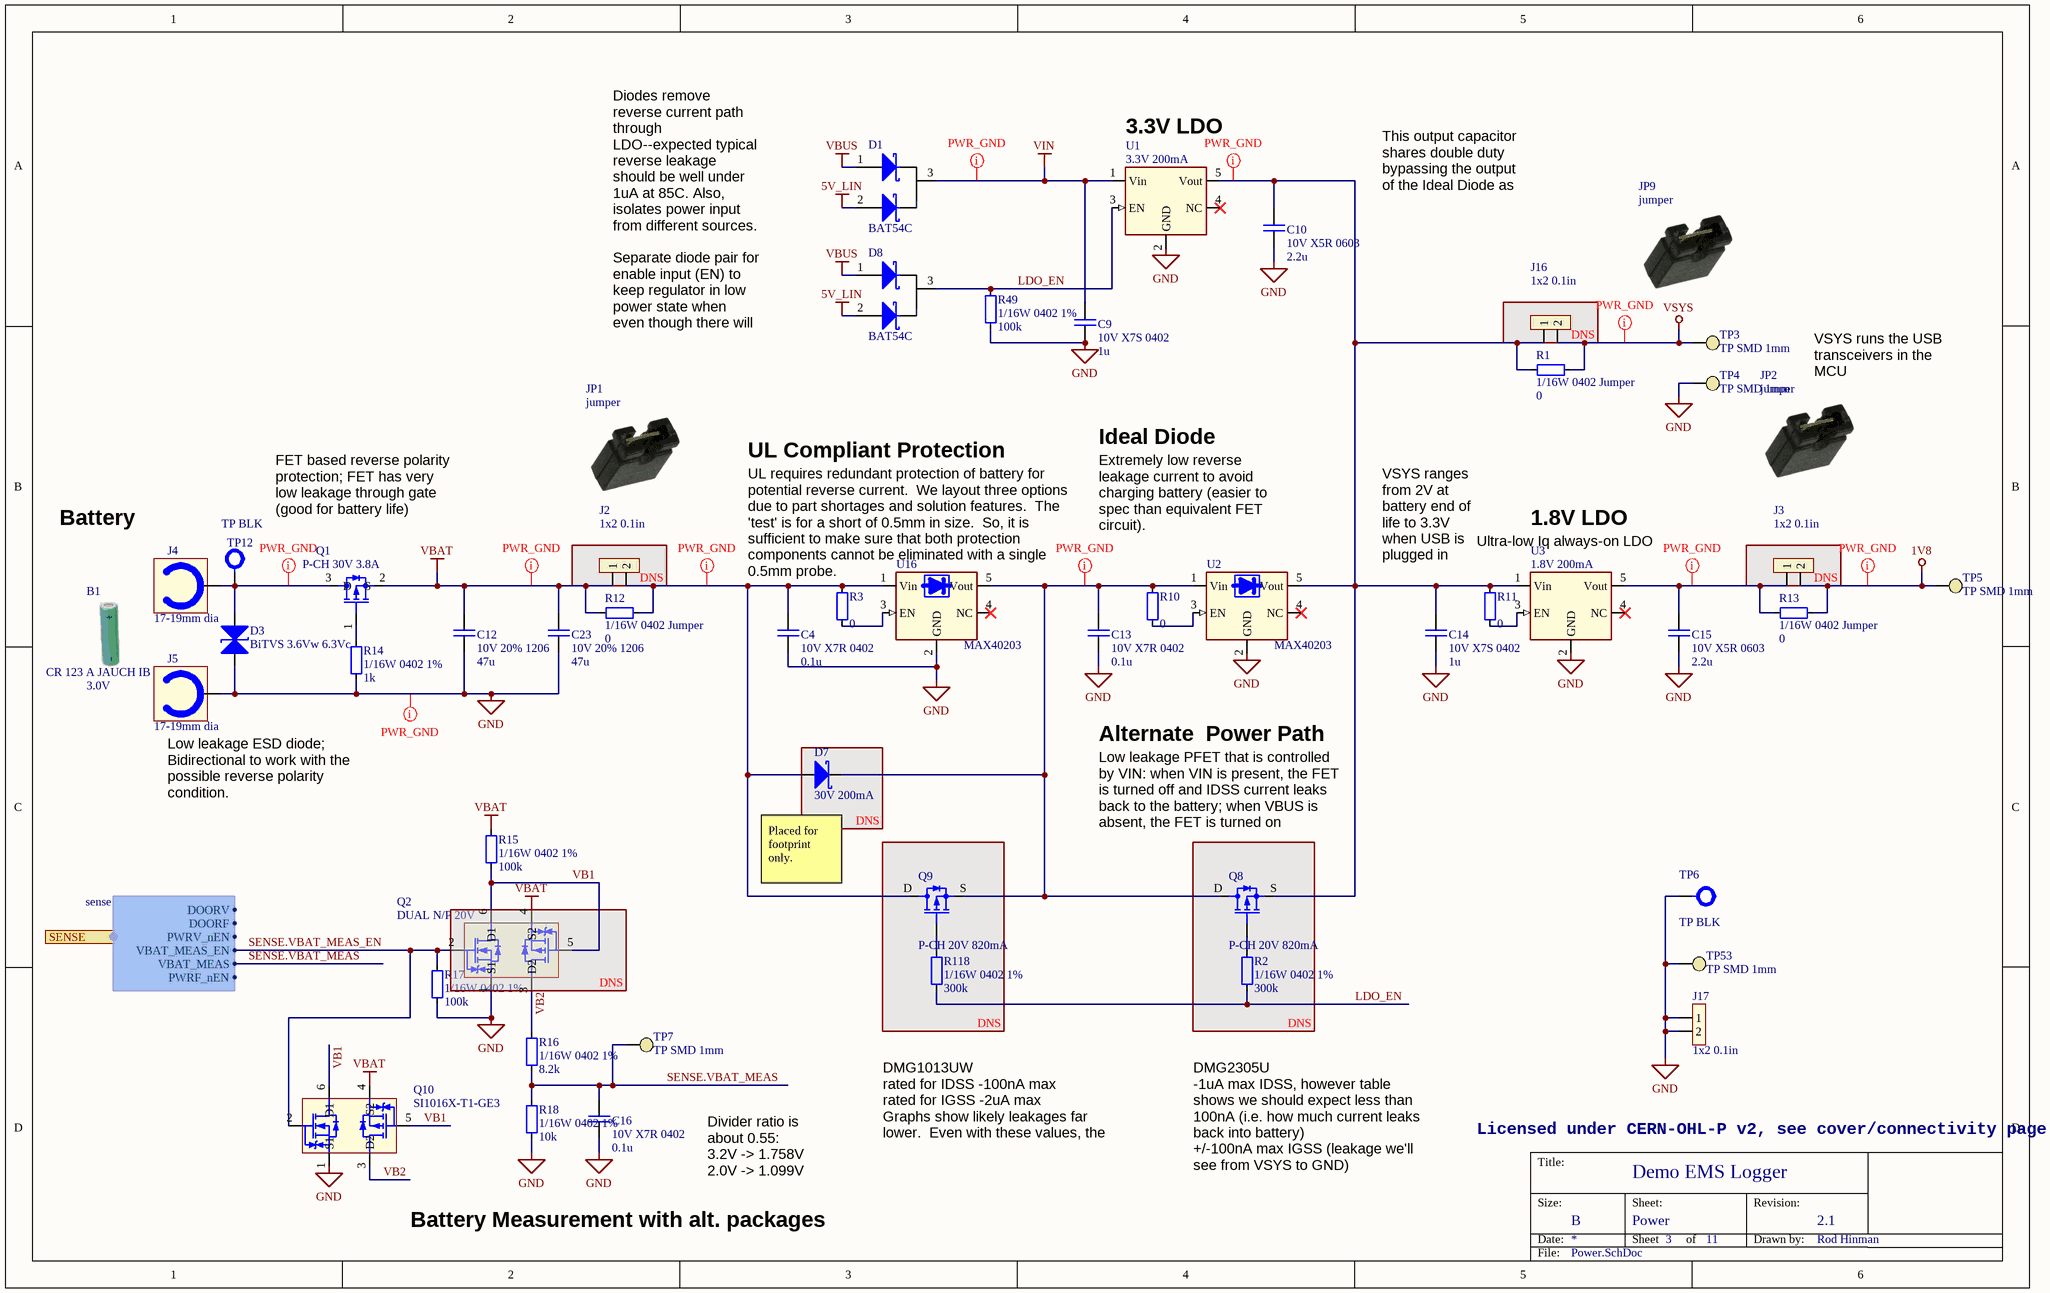
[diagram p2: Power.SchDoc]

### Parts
B1  3.0V  manufacturer_pn: CR 123 A JAUCH IB  (mechanical)
C4  10V X7R 0402  value_text: 0.1u  [CAPC1005X55,0402,L]
C9  10V X7S 0402  value_text: 1u  [CAPC1005X55,0402,L]
C10  10V X5R 0603  value_text: 2.2u  [CAPC1608X100,0603,L]
C12  10V 20% 1206  value_text: 47u  [CAPC3216X190,1206,L]
C13  10V X7R 0402  value_text: 0.1u  [CAPC1005X55,0402,L]
C14  10V X7S 0402  value_text: 1u  [CAPC1005X55,0402,L]
C15  10V X5R 0603  value_text: 2.2u  [CAPC1608X100,0603,L]
C16  10V X7R 0402  value_text: 0.1u  [CAPC1005X55,0402,L]
C23  10V 20% 1206  value_text: 47u  [CAPC3216X190,1206,L]
D1  BAT54C  [SOT23-3B]
D3  BiTVS 3.6Vw 6.3Vc  [TI_2-X1SON]
D7  30V 200mA  [SOD-523_130x90x70]
D8  BAT54C  [SOT23-3B]
J2  1x2 0.1in  [HDR_2PIN]
J3  1x2 0.1in  [HDR_2PIN]
J4  17-19mm dia  [KEYSTONE_254]
J5  17-19mm dia  [KEYSTONE_254]
J16  1x2 0.1in  [HDR_2PIN]
J17  1x2 0.1in  [HDR_2PIN]
JP1  jumper  [SULLINS_QPC02SXGN-RC]
JP2  jumper  [SULLINS_QPC02SXGN-RC]
JP9  jumper  [SULLINS_QPC02SXGN-RC]
Q1  P-CH 30V 3.8A  [SOT23-3]
Q2  DUAL N/P 20V  [SOT363]
Q8  P-CH 20V 820mA  [SOT323_65P200X125x100-GSD]
Q9  P-CH 20V 820mA  [SOT323_65P200X125x100-GSD]
Q10  manufacturer_pn: SI1016X-T1-GE3  [VISHAY_SOT563F_SOTFL50P160X60-6N]  (hidden comment: DUAL N/P 20V)
R1  1/16W 0402 Jumper  value_text: 0  [RESC1005X40,0402,L]
R2  1/16W 0402 1%  value_text: 300k  [RESC1005X40,0402,L]
R3  value_text: 0  [RESC1005X40,0402,L]  (hidden comment: 1/16W 0402 Jumper)
R10  value_text: 0  [RESC1005X40,0402,L]  (hidden comment: 1/16W 0402 Jumper)
R11  value_text: 0  [RESC1005X40,0402,L]  (hidden comment: 1/16W 0402 Jumper)
R12  1/16W 0402 Jumper  value_text: 0  [RESC1005X40,0402,L]
R13  1/16W 0402 Jumper  value_text: 0  [RESC1005X40,0402,L]
R14  1/16W 0402 1%  value_text: 1k  [RESC1005X40,0402,L]
R15  1/16W 0402 1%  value_text: 100k  [RESC1005X40,0402,L]
R16  1/16W 0402 1%  value_text: 8.2k  [RESC1005X40,0402,L]
R17  1/16W 0402 1%  value_text: 100k  [RESC1005X40,0402,L]
R18  1/16W 0402 1%  value_text: 10k  [RESC1005X40,0402,L]
R49  1/16W 0402 1%  value_text: 100k  [RESC1005X40,0402,L]
R118  1/16W 0402 1%  value_text: 300k  [RESC1005X40,0402,L]
TP3  TP SMD 1mm  [TP_SMD_Ø1.0mm NO SILK]  (no BOM)
TP4  TP SMD 1mm  [TP_SMD_Ø1.0mm NO SILK]  (no BOM)
TP5  TP SMD 1mm  [TP_SMD_Ø1.0mm NO SILK]  (no BOM)
TP6  TP BLK  [KEYSTONE_5011]
TP7  TP SMD 1mm  [TP_SMD_Ø1.0mm NO SILK]  (no BOM)
TP12  TP BLK  [KEYSTONE_5011]
TP53  TP SMD 1mm  [TP_SMD_Ø1.0mm NO SILK]  (no BOM)
U1  3.3V 200mA  [TI_SOT-23-5_95P280X145L]
U2  MAX40203  [TI_SOT-23-5_95P280X145L]
U3  1.8V 200mA  [TI_SOT-23-5_95P280X145L]
U16  MAX40203  [TI_SOT-23-5_95P280X145L]

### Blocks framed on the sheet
DNS: J16
DNS: J2
DNS: J3
DNS: D7
DNS: Q9 R118
DNS: Q8 R2
DNS: Q2

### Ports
SENSE (out, harness sense)

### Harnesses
sense: DOORV, DOORF, PWRV_nEN, VBAT_MEAS_EN, VBAT_MEAS, PWRF_nEN

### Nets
1V8: J3.2 R13.2 TP5.1
5V_LIN: D1.2 D8.2
GND: C4.1 C9.1 C10.2 C12.1 C13.1 C14.1 C15.2 C16.1 C23.1 D3.1 J5.1 J17.1 J17.2 Q2.1(S1) Q10.1(S1) R14.2 R17.2 R18.2 R49.2 TP4.1 TP6.1 TP53.1 U1.2(GND) U2.2(GND) U3.2(GND) U16.2(GND)
VBAT: C12.2 C23.2 J2.1 Q1.2(S) Q2.4(S2) Q10.4(S2) R12.1 R15.1
VBUS: D1.1 D8.1
VIN: C9.2 D1.3 U1.1(Vin)
VSYS: J16.2 R1.2 TP3.1
LDO_EN: D8.3 R2.2 R49.1 R118.2 U1.3(EN)
SENSE.VBAT_MEAS: C16.2 R16.2 R18.1 TP7.1 ; port SENSE.VBAT_MEAS
SENSE.VBAT_MEAS_EN: Q2.2(G1) Q10.2(G1) R17.1 ; port SENSE.VBAT_MEAS_EN
VB1: Q2.5(G2) Q2.6(D1) Q10.5(G2) Q10.6(D1) R15.2
VB2: Q2.3(D2) Q10.3(D2) R16.1
NetC4_2: C4.2 D7.A J2.2 Q9.D R3.1 R12.2 U16.1(Vin)
NetC10_1: C10.1 C14.2 J16.1 Q8.S R1.1 R11.1 U1.5(Vout) U2.5(Vout) U3.1(Vin)
NetC13_2: C13.2 D7.K Q8.D Q9.S R10.1 U2.1(Vin) U16.5(Vout)
NetC15_1: C15.1 J3.1 R13.1 U3.5(Vout)
NetD3_2: D3.2 J4.1 Q1.3(D) TP12.1
NetQ1_1: Q1.1(G) R14.1
NetQ8_G: Q8.G R2.1
NetQ9_G: Q9.G R118.1
NetR3_2: R3.2 U16.3(EN)
NetR10_2: R10.2 U2.3(EN)
NetR11_2: R11.2 U3.3(EN)

Not connected (* = marked no-connect by the designer): U1 4(NC)*; U2 4(NC)*; U3 4(NC)*; U16 4(NC)*

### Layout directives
net class PWR_GND: 1V8, GND, NetC4_2, NetC10_1, NetC13_2, NetC15_1, NetD3_2, VBAT, VIN, VSYS

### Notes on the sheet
- (near U1) 3.3V LDO
- This output capacitor shares double duty bypassing the output of the Ideal Diode as well.
- Diodes remove reverse current path through LDO--expected typical reverse leakage should be well under 1uA at 85C. Also, isolates power input from different sources.
  Separate diode pair for enable input (EN) to keep regulator in low power state when even though there will be back conduction through its pass FET.
- VSYS runs the USB transceivers in the MCU
- UL Compliant Protection
- Ideal Diode
- Battery
- FET based reverse polarity protection; FET has very low leakage through gate (good for battery life)
- Extremely low reverse leakage current to avoid charging battery (easier to spec than equivalent FET circuit).
- Ultra-low Iq always-on LDO
- 1.8V LDO
- (near U16) UL requires redundant protection of battery for potential reverse current.  We layout three options due to part shortages and solution features.  The 'test' is for a short of 0.5mm in size.  So, it is sufficient to make sure that both protection components cannot be eliminated with a single 0.5mm probe.
- (near R11) VSYS ranges from 2V at battery end of life to 3.3V when USB is plugged in
- Alternate  Power Path
- Low leakage ESD diode; Bidirectional to work with the possible reverse polarity condition.
- Low leakage PFET that is controlled by VIN: when VIN is present, the FET is turned off and IDSS current leaks back to the battery; when VBUS is absent, the FET is turned on
- (near D7) Placed for footprint only.
- DMG1013UW
  rated for IDSS -100nA max
  rated for IGSS -2uA max
  Graphs show likely leakages far lower.  Even with these values, the battery life and protection should be OK.
- Licensed under CERN-OHL-P v2, see cover/connectivity page.
- Battery Measurement with alt. packages
- Divider ratio is about 0.55:
  3.2V -> 1.758V
  2.0V -> 1.099V
- DMG2305U
  -1uA max IDSS, however table shows we should expect less than 100nA (i.e. how much current leaks back into battery)
  +/-100nA max IGSS (leakage we'll see from VSYS to GND)

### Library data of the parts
B1 = MECH-00043: BATT LITHIUM CYLINDRICAL 3.0V; manufacturer: Jauch Quartz; id: 468241
C4 C13 C16 = CAP-00140: 0.1µF ±10% 10V Ceramic Capacitor X7R 0402 (1005 Metric); manufacturer_pn: CL05B104KP5NNNC; manufacturer: Samsung Electro-Mechanics America, Inc.; id: 479140; value: 1E-7
C9 C14 = CAP-00070: as C3 on sheet MCU
C10 C15 = CAP-00137: CAP CER 2.2UF 10V X5R 0603; manufacturer_pn: CL10A225KP8NNNC; manufacturer: Samsung Electro-Mechanics America, Inc.; id: 468090; value: 2.2E-6
C12 C23 = CAP-00139: CAP CER 47UF 10V X5R 1206; manufacturer_pn: CL31A476MPHNNNE; manufacturer: Samsung Electro-Mechanics America, Inc.; id: 468092; value: 4.7E-5
D1 D8 = DIO-00052: Diode Array 1 Pair Common Cathode Schottky 30 V 200mA (DC) Surface Mount TO-236-3, SC-59, SOT-23-3; manufacturer_pn: BAT54C,215; manufacturer: Nexperia USA Inc.; id: 460427
D3 = DIO-00049: 8.5V (Typ) Clamp 6.3A (8/20µs) Ipp Tvs Diode Surface Mount 2-X1SON (1x.60); manufacturer_pn: TPD1E1B04DPYR; manufacturer: Texas Instruments; id: 408758
D7 = DIO-00053: DIODE SCHOTTKY 30V 200MA SOD523; manufacturer_pn: NSRLL30XV2T1G; manufacturer: ON Semiconductor; id: 468099
J2 J3 J16 J17 = CONN-00001: 2 Positions Header, Unshrouded Connector 0.100" (2.54mm) Through Hole Gold; manufacturer_pn: 961102-6404-AR; manufacturer: 3M; id: 136490
J4 J5 = CONN-00161: BATTERY CONTACT CLIP 18650 SMD; manufacturer_pn: 254; manufacturer: Keystone Electronics; id: 408415
JP1 JP2 JP9 = MECH-00014: 2 (1 x 2) Position Shunt Connector Black Open Top 0.100" (2.54mm) Gold; manufacturer_pn: QPC02SXGN-RC; manufacturer: Sullins Connector Solutions; id: 138116
Q1 = FET-00028: MOSFET P-CH 30V 3.8A SOT23; manufacturer_pn: DMP3099L-7; manufacturer: Diodes Incorporated; id: 468113
Q2 = FET-00000: MOSFET N/P-CH 20V SOT363; manufacturer_pn: DMG1016UDW-7; manufacturer: Diodes Incorporated; id: 136551
Q8 Q9 = FET-00029: MOSFET P-CH 20V 820MA SOT323; manufacturer_pn: DMG1013UW-7; manufacturer: Diodes Incorporated; id: 468211
Q10 = FET-00030: MOSFET N/P-CH 20V SOT563; manufacturer: Vishay Siliconix; id: 474861
R1 R3 R10-R13 = RES-00093: as R34 on sheet MCU
R2 R118 = RES-00073: RES SMD 300K OHM 1% 1/16W 0402; manufacturer_pn: CRCW0402300KFKED; manufacturer: Vishay Dale; id: 152094; value: 300000
R14 = RES-00090: as R30 on sheet MCU
R15 R17 R49 = RES-00095: as R31 on sheet MCU
R16 = RES-00199: RES 8.2K OHM 1% 1/16W 0402; manufacturer_pn: RC0402FR-078K2L; manufacturer: Yageo; id: 468080; value: 8200
R18 = RES-00094: as R41 on sheet MCU
TP3-TP5 TP7 TP53 = NOBOM-00001: as TP10 on sheet MCU
TP6 TP12 = CONN-00028: TEST POINT PC MULTI PURPOSE BLK; manufacturer: Keystone Electronics; manufacturer_pn: 5011; id: 137441
U1 = ICPWR-00061: IC REG LINEAR 3.3V 200MA SOT23-5; manufacturer_pn: TPS7A2433DBVR; manufacturer: Texas Instruments; id: 468175
U2 U16 = ICPWR-00045: OR Controller Source Selector Switch P-Channel 1:1 SOT-23-5; manufacturer_pn: MAX40203AUK+T; manufacturer: Maxim Integrated; id: 378378
U3 = ICPWR-00062: IC REG LINEAR 1.8V 200MA SOT23-5; manufacturer_pn: TPS7A0518PDBVR; manufacturer: Texas Instruments; id: 468176

## Sheet LIN.SchDoc: Insert Title
size B; DrawnBy: Insert Name; Organization: NH-GG; DocumentNumber: 12345; Revision: 1; SheetNumber: 7; SheetTotal: 11; nhSheetName: LIN Interface
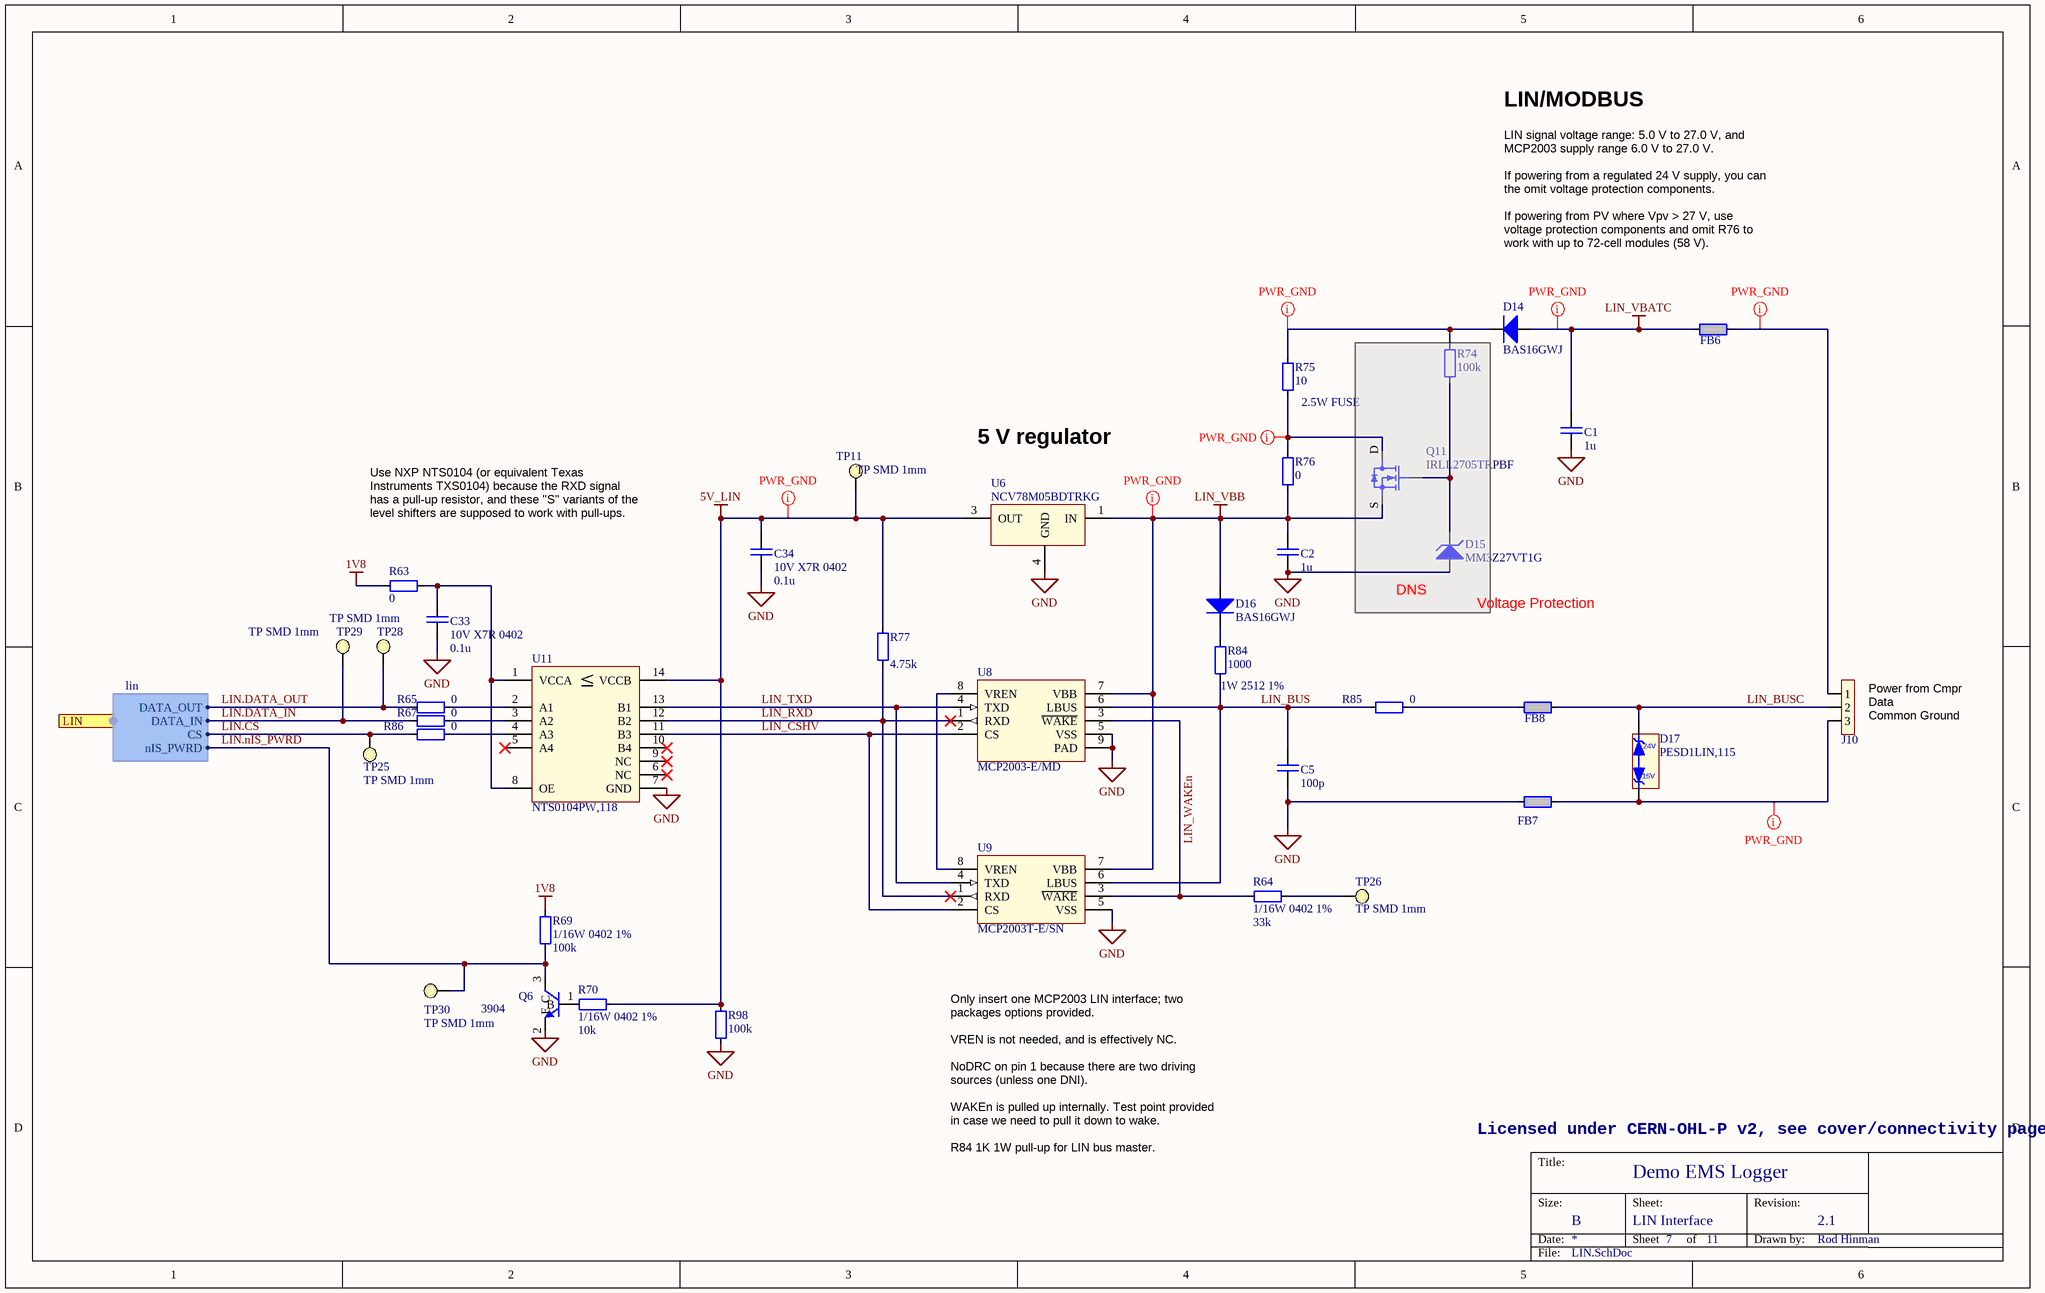
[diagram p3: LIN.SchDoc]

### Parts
C1  value_text: 1u  [CAPC2012X145]  (hidden comment: 50V X7R 0805)
C2  value_text: 1u  [CAPC2012X145]  (hidden comment: 50V X7R 0805)
C5  value_text: 100p  [CAPC1005X55,0402,L]  (hidden comment: 50V C0G 0402)
C33  10V X7R 0402  value_text: 0.1u  [CAPC1005X55,0402,L]
C34  10V X7R 0402  value_text: 0.1u  [CAPC1005X55,0402,L]
D14  manufacturer_pn: BAS16GWJ  [SOD-123]  (hidden comment: 1N4148)
D15  manufacturer_pn: MM3Z27VT1G  [SOD-323]  (hidden comment: 27V 300mW)
D16  manufacturer_pn: BAS16GWJ  [SOD-123]  (hidden comment: 1N4148)
D17  manufacturer_pn: PESD1LIN,115  [NEXPERIA_SOD-323_PESD1LIN]  (hidden comment: PESD1LIN)
FB6  220 Ohm 2A  [FER1608X100,0603,L]  (value not drawn)
FB7  220 Ohm 2A  [FER1608X100,0603,L]  (value not drawn)
FB8  0.49 Ohm 350mA  [FER1005X60,0402,L]  (value not drawn)
J10  JST XH  [JST_S3B-XH-A(LF)(SN)_LESS_SILK]  (value not drawn)
Q6  3904  [SOT23-3]
Q11  manufacturer_pn: IRLL2705TRPBF  [SOT230P700X180-4N_ALPHA]  (hidden comment: N-CH 55V 3.8A)
R63  value_text: 0  [RESC1005X40,0402,L]  (hidden comment: 1/16W 0402 Jumper)
R64  1/16W 0402 1%  value_text: 33k  [RESC1005X40,0402,L]
R65  value_text: 0  [RESC1005X40,0402,L]  (hidden comment: 1/16W 0402 Jumper)
R67  value_text: 0  [RESC1005X40,0402,L]  (hidden comment: 1/16W 0402 Jumper)
R69  1/16W 0402 1%  value_text: 100k  [RESC1005X40,0402,L]
R70  1/16W 0402 1%  value_text: 10k  [RESC1005X40,0402,L]
R74  value_text: 100k  [RESC1005X40,0402,L]  (hidden comment: 1/16W 0402 1%)
R75  2.5W FUSE  value_text: 10  [RESC3216X70[1206]]
R76  value_text: 0  [RESC1005X40,0402,L]  (hidden comment: 1/16W 0402 Jumper)
R77  value_text: 4.75k  [RESC1005X40,0402,L]  (hidden comment: 1/16W 0402 1%)
R84  1W 2512 1%  value_text: 1000  [RESC6534X70[2512]]
R85  value_text: 0  [RESC1005X40,0402,L]  (hidden comment: 1/16W 0402 Jumper)
R86  value_text: 0  [RESC1005X40,0402,L]  (hidden comment: 1/16W 0402 Jumper)
R98  value_text: 100k  [RESC1005X40,0402,L]  (hidden comment: 1/16W 0402 1%)
TP11  TP SMD 1mm  [TP_SMD_Ø1.0mm NO SILK]  (no BOM)
TP25  TP SMD 1mm  [TP_SMD_Ø1.0mm NO SILK]  (no BOM)
TP26  TP SMD 1mm  [TP_SMD_Ø1.0mm NO SILK]  (no BOM)
TP28  TP SMD 1mm  [TP_SMD_Ø1.0mm NO SILK]  (no BOM)
TP29  TP SMD 1mm  [TP_SMD_Ø1.0mm NO SILK]  (no BOM)
TP30  TP SMD 1mm  [TP_SMD_Ø1.0mm NO SILK]  (no BOM)
U6  manufacturer_pn: NCV78M05BDTRKG  [ONSEMI_DPAK229P991X238-3N]  (hidden comment: 35V 5V 0.5A)
U8  manufacturer_pn: MCP2003-E/MD  [SON80P400X100_HS-9N_NOVIA]  (hidden comment: LIN XCV)
U9  manufacturer_pn: MCP2003T-E/SN  [SOIC127P600X170-8N]  (hidden comment: LIN XCV)
U11  manufacturer_pn: NTS0104PW,118  [TSOP65P640X110-14N]  (hidden comment: Logic level translator)

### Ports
LIN (out, harness lin)

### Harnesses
lin: DATA_OUT, DATA_IN, CS, nIS_PWRD

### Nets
1V8: R63.2 R69.1
5V_LIN: C34.2 R70.2 R77.1 R98.1 TP11.1 U6.3(OUT) U11.14(VCCB)
GND: C1.2 C2.2 C5.2 C33.1 C34.1 D15.A FB7.1 Q6.2(E) R98.2 U6.4(GND) U8.5(VSS) U8.9(PAD) U9.5(VSS) U11.7(GND)
LIN_VBATC: C1.1 D14.A FB6.1
LIN_VBB: C2.1 D16.A Q11.S R76.2 U6.1(IN) U8.7(VBB) U9.7(VBB)
LIN.CS: R86.2 TP25.1 ; port LIN.CS
LIN.DATA_IN: R67.2 TP29.1 ; port LIN.DATA_IN
LIN.DATA_OUT: R65.2 TP28.1 ; port LIN.DATA_OUT
LIN.nIS_PWRD: Q6.3(C) R69.2 TP30.1 ; port LIN.nIS_PWRD
LIN_BUS: C5.1 R84.2 R85.2 U8.6(LBUS) U9.6(LBUS)
LIN_BUSC: D17.2 FB8.2 J10.2
LIN_CSHV: U8.2(CS) U9.2(CS) U11.11(B3)
LIN_RXD: R77.2 U8.1(RXD) U9.1(RXD) U11.12(B2)
LIN_TXD: U8.4(TXD) U9.4(TXD) U11.13(B1)
LIN_WAKEn: R64.1 U8.3(~{WAKE}) U9.3(~{WAKE})
NetC33_2: C33.2 R63.1 U11.1(VCCA) U11.8(OE)
NetD14_K: D14.K R74.1 R75.2
NetD15_K: D15.K Q11.G R74.2
NetD16_K: D16.K R84.1
NetD17_1: D17.1 FB7.2 J10.3
NetFB6_2: FB6.2 J10.1
NetFB8_1: FB8.1 R85.1
NetQ6_1: Q6.1(B) R70.1
NetQ11_D: Q11.D R75.1 R76.1
NetR64_2: R64.2 TP26.1
NetR65_1: R65.1 U11.2(A1)
NetR67_1: R67.1 U11.3(A2)
NetR86_1: R86.1 U11.4(A3)
NetU8_8: U8.8(VREN) U9.8(VREN)

Not connected (* = marked no-connect by the designer): U11 5(A4)* 6(NC)* 9(NC)* 10(B4)*

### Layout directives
net class PWR_GND: 5V_LIN, LIN_VBATC, LIN_VBB, NetD14_K, NetD17_1, NetFB6_2, NetQ11_D

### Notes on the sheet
- LIN/MODBUS
- LIN signal voltage range: 5.0 V to 27.0 V, and MCP2003 supply range 6.0 V to 27.0 V.
  If powering from a regulated 24 V supply, you can the omit voltage protection components.
  If powering from PV where Vpv > 27 V, use voltage protection components and omit R76 to work with up to 72-cell modules (58 V).
- 5 V regulator
- (near R63) Use NXP NTS0104 (or equivalent Texas Instruments TXS0104) because the RXD signal has a pull-up resistor, and these "S" variants of the level shifters are supposed to work with pull-ups.
- DNS
- (near D15) Voltage Protection
- (near J10) Power from Cmpr
  Data
  Common Ground
- Only insert one MCP2003 LIN interface; two packages options provided.
  VREN is not needed, and is effectively NC.
  NoDRC on pin 1 because there are two driving sources (unless one DNI).
  WAKEn is pulled up internally. Test point provided in case we need to pull it down to wake.
  R84 1K 1W pull-up for LIN bus master.
- Licensed under CERN-OHL-P v2, see cover/connectivity page.

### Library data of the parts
C1 C2 = CAP-00124: 1µF ±10% 50V Ceramic Capacitor X7R 0805 (2012 Metric); manufacturer: Kemet; manufacturer_pn: C0805C105K5RACTU; id: 403259; value: 1E-6
C5 = CAP-00099: 100pF ±5% 50V Ceramic Capacitor C0G, NP0 0402 (1005 Metric); manufacturer: TDK Corporation; manufacturer_pn: CGA2B2C0G1H101J050BA; id: 225971; value: 1E-10
C33 C34 = CAP-00140: as C4 on sheet Power
D14 D16 = DIO-00040: Diode Standard 100V 215mA (DC) Surface Mount SOD-123; manufacturer: Nexperia USA Inc.; id: 226620
D15 = DIO-00059: DIODE ZENER 27V 300MW SOD323; manufacturer: ON Semiconductor; id: 475650
D17 = DIO-00058: TVS DIODE 15VWM 24VWM SOD323; manufacturer: Nexperia USA Inc.; id: 475649
FB6 FB7 = FER-00004: FERRITE BEAD 220 OHM 0603 1LN 50m ohm; manufacturer_pn: BLM18EG221SN1D; manufacturer: Murata Electronics North America; value_text: 220; id: 137076; reorder_quantity: 0; value: 220
FB8 = FER-00013: FERRITE BEAD 1 KOHM 0402 1LN; manufacturer_pn: BLM15AX102SN1D; manufacturer: Murata Electronics North America; id: 468095; value_text: 1k; value: 1000
J10 = CONN-00186: CONN HEADER R/A 3POS 2.5MM; manufacturer: JST Sales America Inc.; manufacturer_pn: S3B-XH-A(LF)(SN); id: 477185
Q6 = BJT-00000: TRANS NPN 40V 0.2A SOT23; manufacturer_pn: MMBT3904LT1G; manufacturer: ON Semiconductor; id: 138488
Q11 = FET-00032: MOSFET N-CH 55V 3.8A SOT223; manufacturer: Infineon Technologies; id: 475653
R63 R65 R67 R76 R85 R86 = RES-00093: as R34 on sheet MCU
R64 = RES-00198: RES 33K OHM 1% 1/16W 0402; manufacturer_pn: RC0402FR-0733KL; manufacturer: Yageo; id: 468079; value: 33000
R69 R74 R98 = RES-00095: as R31 on sheet MCU
R70 = RES-00094: as R41 on sheet MCU
R75 = RES-00204: RESISTOR FUSIBLE 10 OHMS 1206; manufacturer_pn: FRC32C2B100JTP; manufacturer: Kamaya, Inc; id: 475654; value: 10
R77 = RES-00170: 4.75k ±1% 0.063W, 1/16W Chip Resistor 0402 (1005 Metric) - Thick Film; manufacturer_pn: RC0402FR-074K75L; manufacturer: Yageo; id: 406783; value: 4750
R84 = RES-00196: 1 kOhms ±1% 1W Chip Resistor 2512 (6432 Metric) Automotive AEC-Q200 Thick Film; manufacturer_pn: RMCF2512FT1K00; manufacturer: Stackpole Electronics Inc; id: 460819; value: 1000
TP11 TP25 TP26 TP28-TP30 = NOBOM-00001: as TP10 on sheet MCU
U6 = ICPWR-00063: IC REG LINEAR 5V 500MA DPAK; manufacturer: ON Semiconductor; id: 474985
U8 = ICXCV-00033: LIN Transceiver; manufacturer: Microchip Technology; id: 474960
U9 = ICXCV-00029: LIN Transceiver; manufacturer: Microchip Technology; id: 458277
U11 = ICXCV-00032: IC TRNSLTR BIDIRECTIONAL; manufacturer: NXP Semiconductors; id: 474958

## Sheet Sensors.SchDoc: Insert Title
size B; DrawnBy: Insert Name; Organization: NH-GG; DocumentNumber: 12345; Revision: 1; SheetNumber: 8; SheetTotal: 11; nhSheetName: Sensors
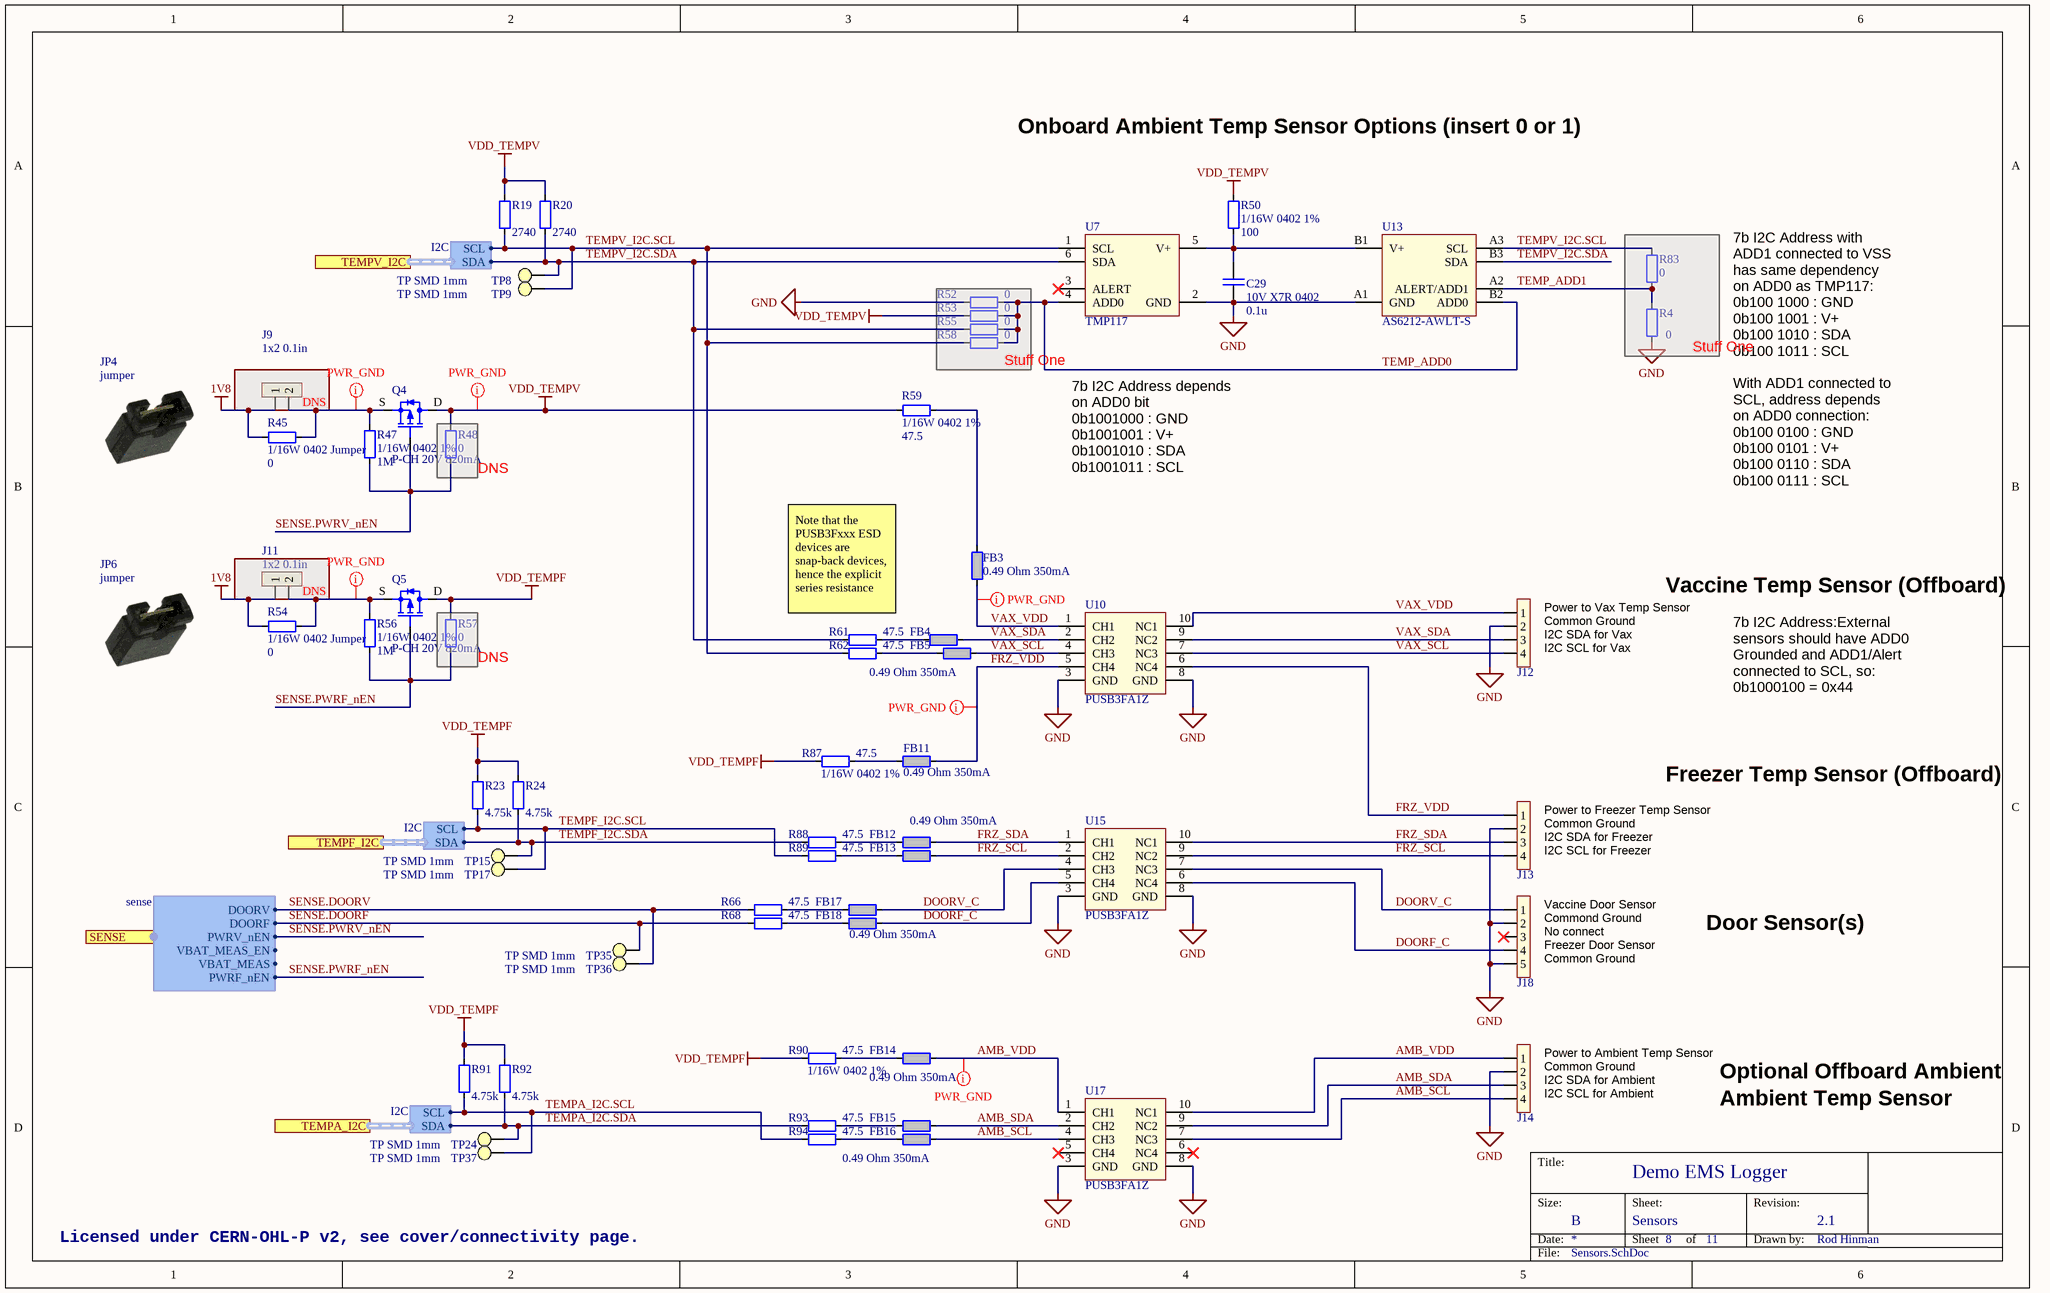
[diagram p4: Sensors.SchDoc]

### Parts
C29  10V X7R 0402  value_text: 0.1u  [CAPC1005X55,0402,L]
FB3  0.49 Ohm 350mA  [FER1005X60,0402,L]
FB4  0.49 Ohm 350mA  [FER1005X60,0402,L]  (value not drawn)
FB5  0.49 Ohm 350mA  [FER1005X60,0402,L]
FB11  0.49 Ohm 350mA  [FER1005X60,0402,L]
FB12  0.49 Ohm 350mA  [FER1005X60,0402,L]  (value not drawn)
FB13  0.49 Ohm 350mA  [FER1005X60,0402,L]
FB14  0.49 Ohm 350mA  [FER1005X60,0402,L]
FB15  0.49 Ohm 350mA  [FER1005X60,0402,L]  (value not drawn)
FB16  0.49 Ohm 350mA  [FER1005X60,0402,L]
FB17  0.49 Ohm 350mA  [FER1005X60,0402,L]  (value not drawn)
FB18  0.49 Ohm 350mA  [FER1005X60,0402,L]
J9  1x2 0.1in  [HDR_2PIN]
J11  1x2 0.1in  [HDR_2PIN]
J12  JST XH  [JST_S4B-XH-A(LF)(SN)_LESS_SILK]  (value not drawn)
J13  JST XH  [JST_S4B-XH-A(LF)(SN)_LESS_SILK]  (value not drawn)
J14  JST XH  [JST_S4B-XH-A(LF)(SN)_LESS_SILK]  (value not drawn)
J18  JST XH  [JST_S5B-XH-A(LF)(SN)_LESS_SILK]  (value not drawn)
JP4  jumper  [SULLINS_QPC02SXGN-RC]
JP6  jumper  [SULLINS_QPC02SXGN-RC]
Q4  P-CH 20V 820mA  [SOT323_65P200X125x100-GSD]
Q5  P-CH 20V 820mA  [SOT323_65P200X125x100-GSD]
R4  value_text: 0  [RESC1005X40,0402,L]  (hidden comment: 1/16W 0402 Jumper)
R19  value_text: 2740  [RESC1005X40,0402,L]  (hidden comment: 1/16W 0402 1%)
R20  value_text: 2740  [RESC1005X40,0402,L]  (hidden comment: 1/16W 0402 1%)
R23  value_text: 4.75k  [RESC1005X40,0402,L]  (hidden comment: 1/16W 0402 1%)
R24  value_text: 4.75k  [RESC1005X40,0402,L]  (hidden comment: 1/16W 0402 1%)
R45  1/16W 0402 Jumper  value_text: 0  [RESC1005X40,0402,L]
R47  1/16W 0402 1%  value_text: 1M  [RESC1005X40,0402,L]
R48  value_text: 0  [RESC1005X40,0402,L]  (hidden comment: 1/16W 0402 Jumper)
R50  1/16W 0402 1%  value_text: 100  [RESC1005X40,0402,L]
R52  value_text: 0  [RESC1005X40,0402,L]  (hidden comment: 1/16W 0402 Jumper)
R53  value_text: 0  [RESC1005X40,0402,L]  (hidden comment: 1/16W 0402 Jumper)
R54  1/16W 0402 Jumper  value_text: 0  [RESC1005X40,0402,L]
R55  value_text: 0  [RESC1005X40,0402,L]  (hidden comment: 1/16W 0402 Jumper)
R56  1/16W 0402 1%  value_text: 1M  [RESC1005X40,0402,L]
R57  value_text: 0  [RESC1005X40,0402,L]  (hidden comment: 1/16W 0402 Jumper)
R58  value_text: 0  [RESC1005X40,0402,L]  (hidden comment: 1/16W 0402 Jumper)
R59  1/16W 0402 1%  value_text: 47.5  [RESC1005X40,0402,L]
R61  value_text: 47.5  [RESC1005X40,0402,L]  (hidden comment: 1/16W 0402 1%)
R62  value_text: 47.5  [RESC1005X40,0402,L]  (hidden comment: 1/16W 0402 1%)
R66  value_text: 47.5  [RESC1005X40,0402,L]  (hidden comment: 1/16W 0402 1%)
R68  value_text: 47.5  [RESC1005X40,0402,L]  (hidden comment: 1/16W 0402 1%)
R83  value_text: 0  [RESC1005X40,0402,L]  (hidden comment: 1/16W 0402 Jumper)
R87  1/16W 0402 1%  value_text: 47.5  [RESC1005X40,0402,L]
R88  value_text: 47.5  [RESC1005X40,0402,L]  (hidden comment: 1/16W 0402 1%)
R89  value_text: 47.5  [RESC1005X40,0402,L]  (hidden comment: 1/16W 0402 1%)
R90  1/16W 0402 1%  value_text: 47.5  [RESC1005X40,0402,L]
R91  value_text: 4.75k  [RESC1005X40,0402,L]  (hidden comment: 1/16W 0402 1%)
R92  value_text: 4.75k  [RESC1005X40,0402,L]  (hidden comment: 1/16W 0402 1%)
R93  value_text: 47.5  [RESC1005X40,0402,L]  (hidden comment: 1/16W 0402 1%)
R94  value_text: 47.5  [RESC1005X40,0402,L]  (hidden comment: 1/16W 0402 1%)
TP8  TP SMD 1mm  [TP_SMD_Ø1.0mm NO SILK]  (no BOM)
TP9  TP SMD 1mm  [TP_SMD_Ø1.0mm NO SILK]  (no BOM)
TP15  TP SMD 1mm  [TP_SMD_Ø1.0mm NO SILK]  (no BOM)
TP17  TP SMD 1mm  [TP_SMD_Ø1.0mm NO SILK]  (no BOM)
TP24  TP SMD 1mm  [TP_SMD_Ø1.0mm NO SILK]  (no BOM)
TP35  TP SMD 1mm  [TP_SMD_Ø1.0mm NO SILK]  (no BOM)
TP36  TP SMD 1mm  [TP_SMD_Ø1.0mm NO SILK]  (no BOM)
TP37  TP SMD 1mm  [TP_SMD_Ø1.0mm NO SILK]  (no BOM)
U7  TMP117  [TI-TMP117-WSON]
U10  PUSB3FA1Z  [NEXPERIA_DFN2510_50p250x100x50-10]
U13  manufacturer_pn: AS6212-AWLT-S  [AMS_BGA6C40P3X2_150X102X60]  (hidden comment: AMS_AS621x)
U15  PUSB3FA1Z  [NEXPERIA_DFN2510_50p250x100x50-10]
U17  PUSB3FA1Z  [NEXPERIA_DFN2510_50p250x100x50-10]

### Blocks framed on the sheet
Stuff One: R4 R83
Stuff One: R52 R53 R55 R58
DNS: J9
DNS: J11

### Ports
SENSE (out, harness sense), TEMPA_I2C (harness I2C), TEMPF_I2C (harness I2C), TEMPV_I2C (harness I2C)

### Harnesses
I2C: SCL, SDA
sense: DOORV, DOORF, PWRV_nEN, VBAT_MEAS_EN, VBAT_MEAS, PWRF_nEN

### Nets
1V8: J9.1 J11.1 R45.1 R54.1
GND: C29.1 J12.2 J13.2 J14.2 J18.2 J18.5 R4.2 R52.2 U7.2(GND) U10.3(GND) U10.8(GND) U13.A1(GND) U15.3(GND) U15.8(GND) U17.3(GND) U17.8(GND)
VDD_TEMPF: Q5.D R23.1 R24.1 R57.1 R87.1 R90.1 R91.1 R92.1
VDD_TEMPV: Q4.D R19.1 R20.1 R48.1 R50.1 R53.2 R59.1
AMB_SCL: FB16.2 J14.4 U17.4(CH3) U17.7(NC3)
AMB_SDA: FB15.2 J14.3 U17.2(CH2) U17.9(NC2)
AMB_VDD: FB14.2 J14.1 U17.1(CH1) U17.10(NC1)
DOORF_C: FB18.2 J18.4 U15.5(CH4) U15.6(NC4)
DOORV_C: FB17.2 J18.1 U15.4(CH3) U15.7(NC3)
FRZ_SCL: FB13.2 J13.4 U15.2(CH2) U15.9(NC2)
FRZ_SDA: FB12.2 J13.3 U15.1(CH1) U15.10(NC1)
FRZ_VDD: FB11.2 J13.1 U10.5(CH4) U10.6(NC4)
SENSE.DOORF: R68.1 TP35.1 ; port SENSE.DOORF
SENSE.DOORV: R66.1 TP36.1 ; port SENSE.DOORV
SENSE.PWRF_nEN: Q5.G R56.2 R57.2 ; port SENSE.PWRF_nEN
SENSE.PWRV_nEN: Q4.G R47.2 R48.2 ; port SENSE.PWRV_nEN
TEMP_ADD0: R52.1 R53.1 R55.1 R58.1 U7.4(ADD0) U13.B2(ADD0)
TEMP_ADD1: R4.1 R83.2 U13.A2(ALERT/ADD1)
TEMPA_I2C.SCL: R91.2 R94.1 TP37.1 ; port TEMPA_I2C.SCL
TEMPA_I2C.SDA: R92.2 R93.1 TP24.1 ; port TEMPA_I2C.SDA
TEMPF_I2C.SCL: R23.2 R89.1 TP17.1 ; port TEMPF_I2C.SCL
TEMPF_I2C.SDA: R24.2 R88.1 TP15.1 ; port TEMPF_I2C.SDA
TEMPV_I2C.SCL: R19.2 R58.2 R62.1 R83.1 TP9.1 U7.1(SCL) U13.A3(SCL) ; port TEMPV_I2C.SCL
TEMPV_I2C.SDA: R20.2 R55.2 R61.1 TP8.1 U7.6(SDA) U13.B3(SDA) ; port TEMPV_I2C.SDA
VAX_SCL: FB5.2 J12.4 U10.4(CH3) U10.7(NC3)
VAX_SDA: FB4.2 J12.3 U10.2(CH2) U10.9(NC2)
VAX_VDD: FB3.2 J12.1 U10.1(CH1) U10.10(NC1)
NetC29_2: C29.2 R50.2 U7.5(V+) U13.B1(V+)
NetFB3_1: FB3.1 R59.2
NetFB4_1: FB4.1 R61.2
NetFB5_1: FB5.1 R62.2
NetFB11_1: FB11.1 R87.2
NetFB12_1: FB12.1 R88.2
NetFB13_1: FB13.1 R89.2
NetFB14_1: FB14.1 R90.2
NetFB15_1: FB15.1 R93.2
NetFB16_1: FB16.1 R94.2
NetFB17_1: FB17.1 R66.2
NetFB18_1: FB18.1 R68.2
NetJ9_2: J9.2 Q4.S R45.2 R47.1
NetJ11_2: J11.2 Q5.S R54.2 R56.1

Not connected (* = marked no-connect by the designer): J18 3*; U7 3(ALERT)*; U17 5(CH4)* 6(NC4)*

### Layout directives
net class PWR_GND: AMB_VDD, FRZ_VDD, NetJ9_2, NetJ11_2, VAX_VDD, VDD_TEMPV

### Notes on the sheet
- Onboard Ambient Temp Sensor Options (insert 0 or 1)
- (near R48) DNS
- 7b I2C Address depends on ADD0 bit
  0b1001000 : GND
  0b1001001 : V+
  0b1001010 : SDA
  0b1001011 : SCL
- 7b I2C Address with ADD1 connected to VSS has same dependency on ADD0 as TMP117:
  0b100 1000 : GND
  0b100 1001 : V+
  0b100 1010 : SDA
  0b100 1011 : SCL
  With ADD1 connected to SCL, address depends on ADD0 connection:
  0b100 0100 : GND
  0b100 0101 : V+
  0b100 0110 : SDA
  0b100 0111 : SCL
- Note that the PUSB3Fxxx ESD devices are snap-back devices, hence the explicit series resistance
- Vaccine Temp Sensor (Offboard)
- (near R57) DNS
- (near J12) Power to Vax Temp Sensor
  Common Ground
  I2C SDA for Vax
  I2C SCL for Vax
- 7b I2C Address:External sensors should have ADD0 Grounded and ADD1/Alert connected to SCL, so:
  0b1000100 = 0x44
- Freezer Temp Sensor (Offboard)
- (near J13) Power to Freezer Temp Sensor
  Common Ground
  I2C SDA for Freezer
  I2C SCL for Freezer
- (near J18) Vaccine Door Sensor
  Commond Ground
  No connect
  Freezer Door Sensor
  Common Ground
- Door Sensor(s)
- (near J14) Power to Ambient Temp Sensor
  Common Ground
  I2C SDA for Ambient
  I2C SCL for Ambient
- Optional Offboard Ambient
- Ambient Temp Sensor
- Licensed under CERN-OHL-P v2, see cover/connectivity page.

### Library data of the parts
C29 = CAP-00140: as C4 on sheet Power
FB3-FB5 FB11-FB18 = FER-00013: as FB8 on sheet LIN
J9 J11 = CONN-00001: as J2 on sheet Power
J12-J14 = CONN-00005: 4 Positions Header, Shrouded Connector 0.098" (2.50mm) Through Hole, Right Angle Tin; manufacturer_pn: S4B-XH-A(LF)(SN); manufacturer: JST Sales America Inc.; id: 136790
J18 = CONN-00187: CONN HEADER R/A 5POS 2.5MM; manufacturer_pn: S5B-XH-A(LF)(SN); manufacturer: JST Sales America Inc.; id: 477186
JP4 JP6 = MECH-00014: as JP1 on sheet Power
Q4 Q5 = FET-00029: as Q8 on sheet Power
R4 R45 R48 R52-R55 R57 R58 R83 = RES-00093: as R34 on sheet MCU
R19 R20 = RES-00205: RES 2.74K OHM 1% 1/16W 0402; manufacturer_pn: RC0402FR-072K74L; manufacturer: Yageo; id: 475656; value: 2740
R23 R24 R91 R92 = RES-00170: as R77 on sheet LIN
R47 R56 = RES-00137: 1 MOhms ±1% 0.063W, 1/16W Chip Resistor 0402 (1005 Metric) Automotive AEC-Q200 Thick Film; manufacturer_pn: RC0402FR-071ML; manufacturer: Vishay Dale; id: 225970; value: 1000000
R50 = RES-00111: as R44 on sheet MCU
R59 R61 R62 R66 R68 R87-R90 R93 R94 = RES-00169: as R35 on sheet MCU
TP8 TP9 TP15 TP17 TP24 TP35-TP37 = NOBOM-00001: as TP10 on sheet MCU
U7 = ICANA-00030: Temperature Sensor Digital, Local -55°C ~ 150°C 16 b 6-WSON (2x2); manufacturer_pn: TMP117NAIDRVR; manufacturer: Texas Instruments; id: 367218
U10 U15 U17 = DIO-00056: as U5 on sheet MCU
U13 = ICANA-00040: TEMP SENSOR WLCSP6 I2C; manufacturer: AMS; id: 474864

## Sheet Flash.SchDoc: Insert Title
size B; DrawnBy: Insert Name; Organization: NH-GG; DocumentNumber: 12345; Revision: 1; SheetNumber: 6; SheetTotal: 11; nhSheetName: Flash
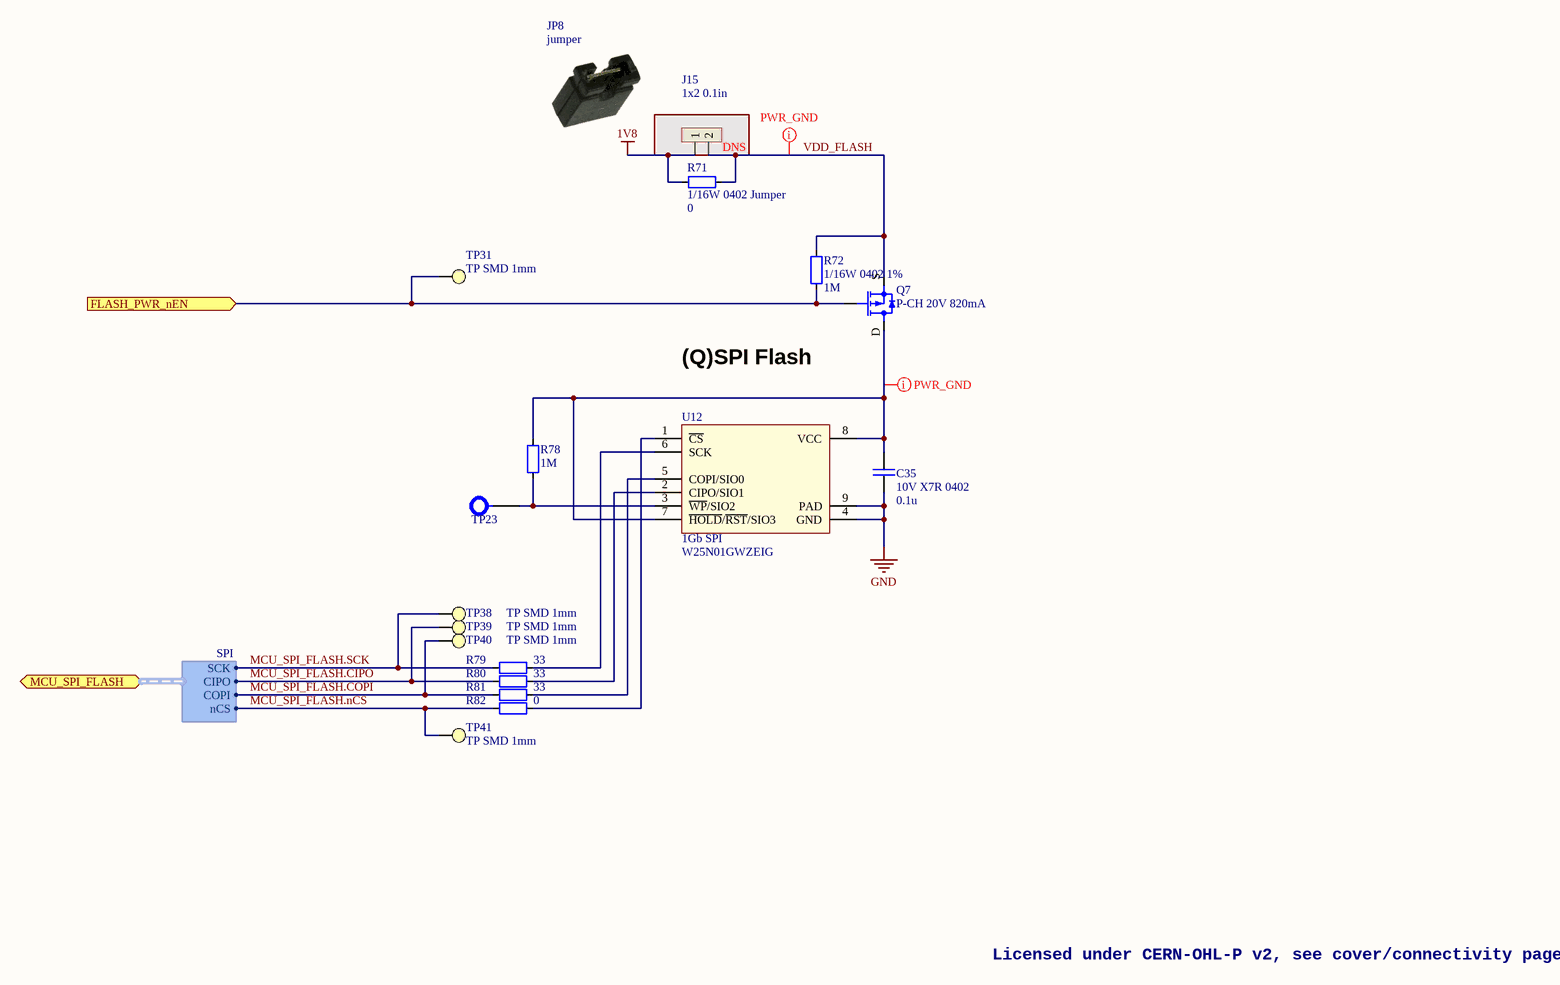
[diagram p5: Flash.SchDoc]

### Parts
C35  10V X7R 0402  value_text: 0.1u  [CAPC1005X55,0402,L]
J15  1x2 0.1in  [HDR_2PIN]
JP8  jumper  [SULLINS_QPC02SXGN-RC]
Q7  P-CH 20V 820mA  [SOT323_65P200X125x100-GSD]
R71  1/16W 0402 Jumper  value_text: 0  [RESC1005X40,0402,L]
R72  1/16W 0402 1%  value_text: 1M  [RESC1005X40,0402,L]
R78  value_text: 1M  [RESC1005X40,0402,L]  (hidden comment: 1/16W 0402 1%)
R79  value_text: 33  [RESC1005X40,0402,L]  (hidden comment: 1/16W 0402 1%)
R80  value_text: 33  [RESC1005X40,0402,L]  (hidden comment: 1/16W 0402 1%)
R81  value_text: 33  [RESC1005X40,0402,L]  (hidden comment: 1/16W 0402 1%)
R82  value_text: 0  [RESC1005X40,0402,L]  (hidden comment: 1/16W 0402 Jumper)
TP23  TP TH  0.78mm  [TP_TH078H127P]  (value not drawn)  (no BOM)
TP31  TP SMD 1mm  [TP_SMD_Ø1.0mm NO SILK]  (no BOM)
TP38  TP SMD 1mm  [TP_SMD_Ø1.0mm NO SILK]  (no BOM)
TP39  TP SMD 1mm  [TP_SMD_Ø1.0mm NO SILK]  (no BOM)
TP40  TP SMD 1mm  [TP_SMD_Ø1.0mm NO SILK]  (no BOM)
TP41  TP SMD 1mm  [TP_SMD_Ø1.0mm NO SILK]  (no BOM)
U12  1Gb SPI  manufacturer_pn: W25N01GWZEIG  [SON127P800X95_HS-9N_no_via]

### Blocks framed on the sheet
DNS: J15

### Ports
FLASH_PWR_nEN (in), MCU_SPI_FLASH (bidir, harness SPI)

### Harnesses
SPI: CIPO, COPI, SCK, nCS

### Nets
1V8: J15.1 R71.1
GND: C35.1 U12.4(GND) U12.9(PAD)
FLASH_PWR_nEN: Q7.G R72.2 TP31.1 ; port FLASH_PWR_nEN
MCU_SPI_FLASH.CIPO: R80.1 TP39.1 ; port MCU_SPI_FLASH.CIPO
MCU_SPI_FLASH.COPI: R81.1 TP40.1 ; port MCU_SPI_FLASH.COPI
MCU_SPI_FLASH.nCS: R82.2 TP41.1 ; port MCU_SPI_FLASH.nCS
MCU_SPI_FLASH.SCK: R79.1 TP38.1 ; port MCU_SPI_FLASH.SCK
VDD_FLASH: J15.2 Q7.S R71.2 R72.1
NetC35_2: C35.2 Q7.D R78.2 U12.7(~{HOLD}/~{RST}/SIO3) U12.8(VCC)
NetR78_1: R78.1 TP23.1 U12.3(~{WP}/SIO2)
NetR79_2: R79.2 U12.6(SCK)
NetR80_2: R80.2 U12.2(CIPO/SIO1)
NetR81_2: R81.2 U12.5(COPI/SIO0)
NetR82_1: R82.1 U12.1(~{CS})

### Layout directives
net class PWR_GND: NetC35_2, VDD_FLASH

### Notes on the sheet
- (Q)SPI Flash
- Licensed under CERN-OHL-P v2, see cover/connectivity page.

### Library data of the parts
C35 = CAP-00140: as C4 on sheet Power
J15 = CONN-00001: as J2 on sheet Power
JP8 = MECH-00014: as JP1 on sheet Power
Q7 = FET-00029: as Q8 on sheet Power
R71 R82 = RES-00093: as R34 on sheet MCU
R72 R78 = RES-00137: as R47 on sheet Sensors
R79-R81 = RES-00201: RES 33 OHM 1% 1/16W 0402; manufacturer_pn: RC0402FR-0733RL; manufacturer: Yageo; id: 468082; value: 33
TP23 = NOBOM-00007: Test point, TH, 0.78mm (30mil) hole, 1.27mm (50 mil) pad; manufacturer: New Horizons; id: 137437
TP31 TP38-TP41 = NOBOM-00001: as TP10 on sheet MCU
U12 = ICDIG-00028: IC FLASH 1GBIT SPI 104MHZ 8WSON 1.8V; manufacturer: Winbond Electronics; id: 474863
